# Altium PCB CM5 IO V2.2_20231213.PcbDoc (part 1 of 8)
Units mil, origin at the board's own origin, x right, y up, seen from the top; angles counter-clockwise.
Board outline 6299.61 x 3544.09 mil, 4 copper layers (Top, GND, Power, Bottom), stack 35.4 mil thick; 482 components, 404 nets, 1857 pads, 2731 vias.
Unrouted connection lines stored in the file: 1872.
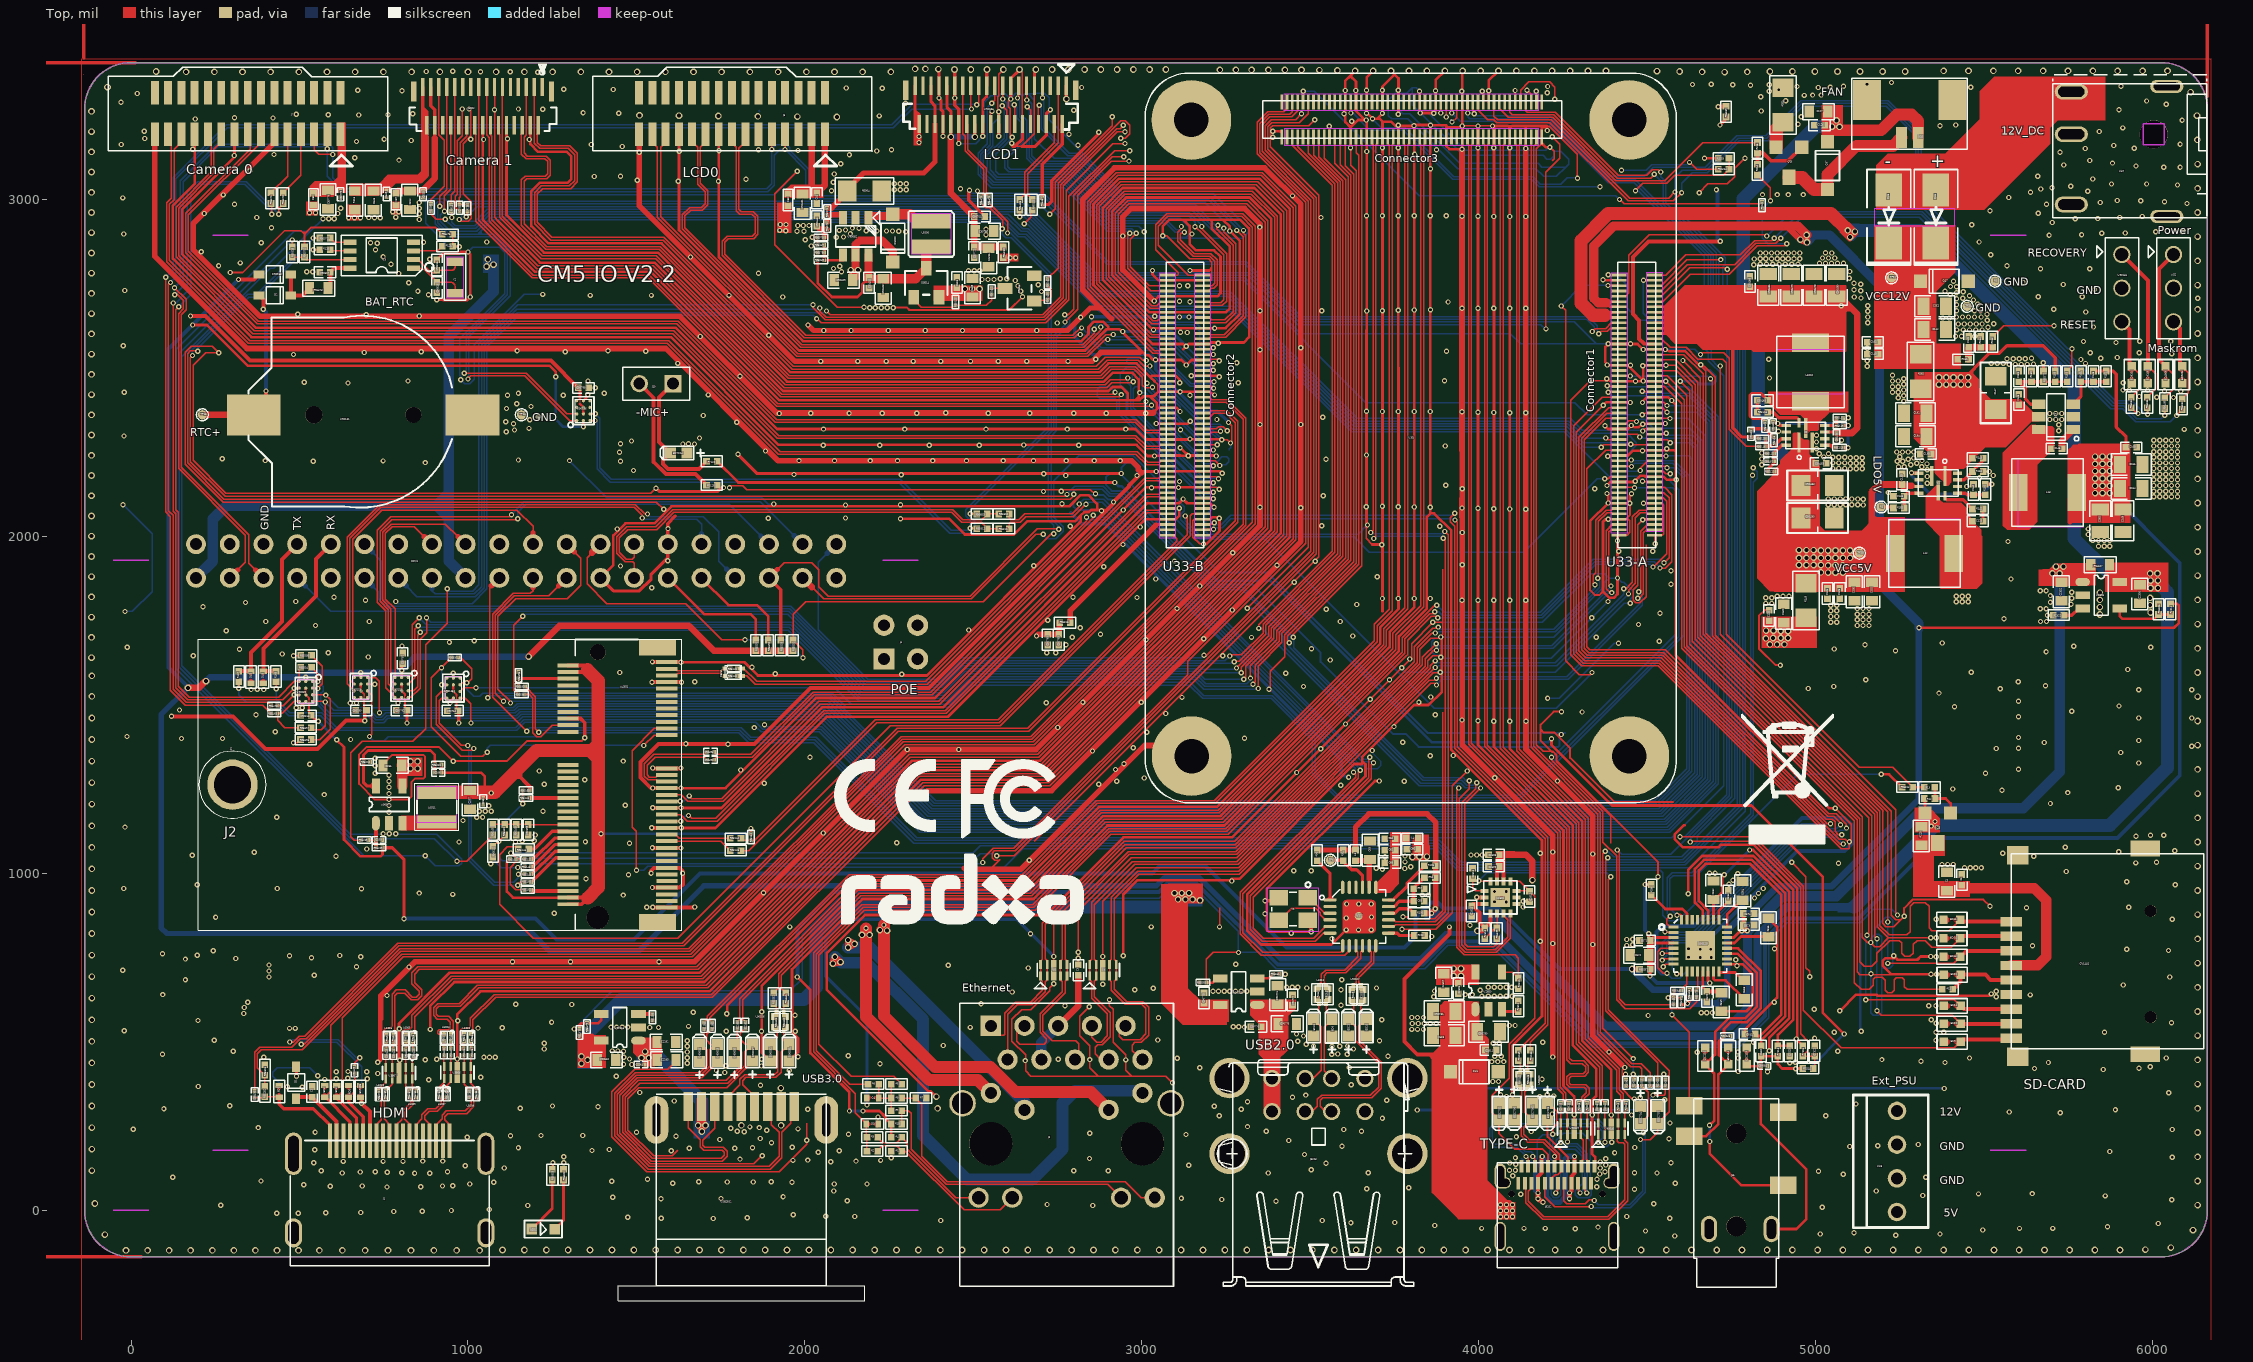
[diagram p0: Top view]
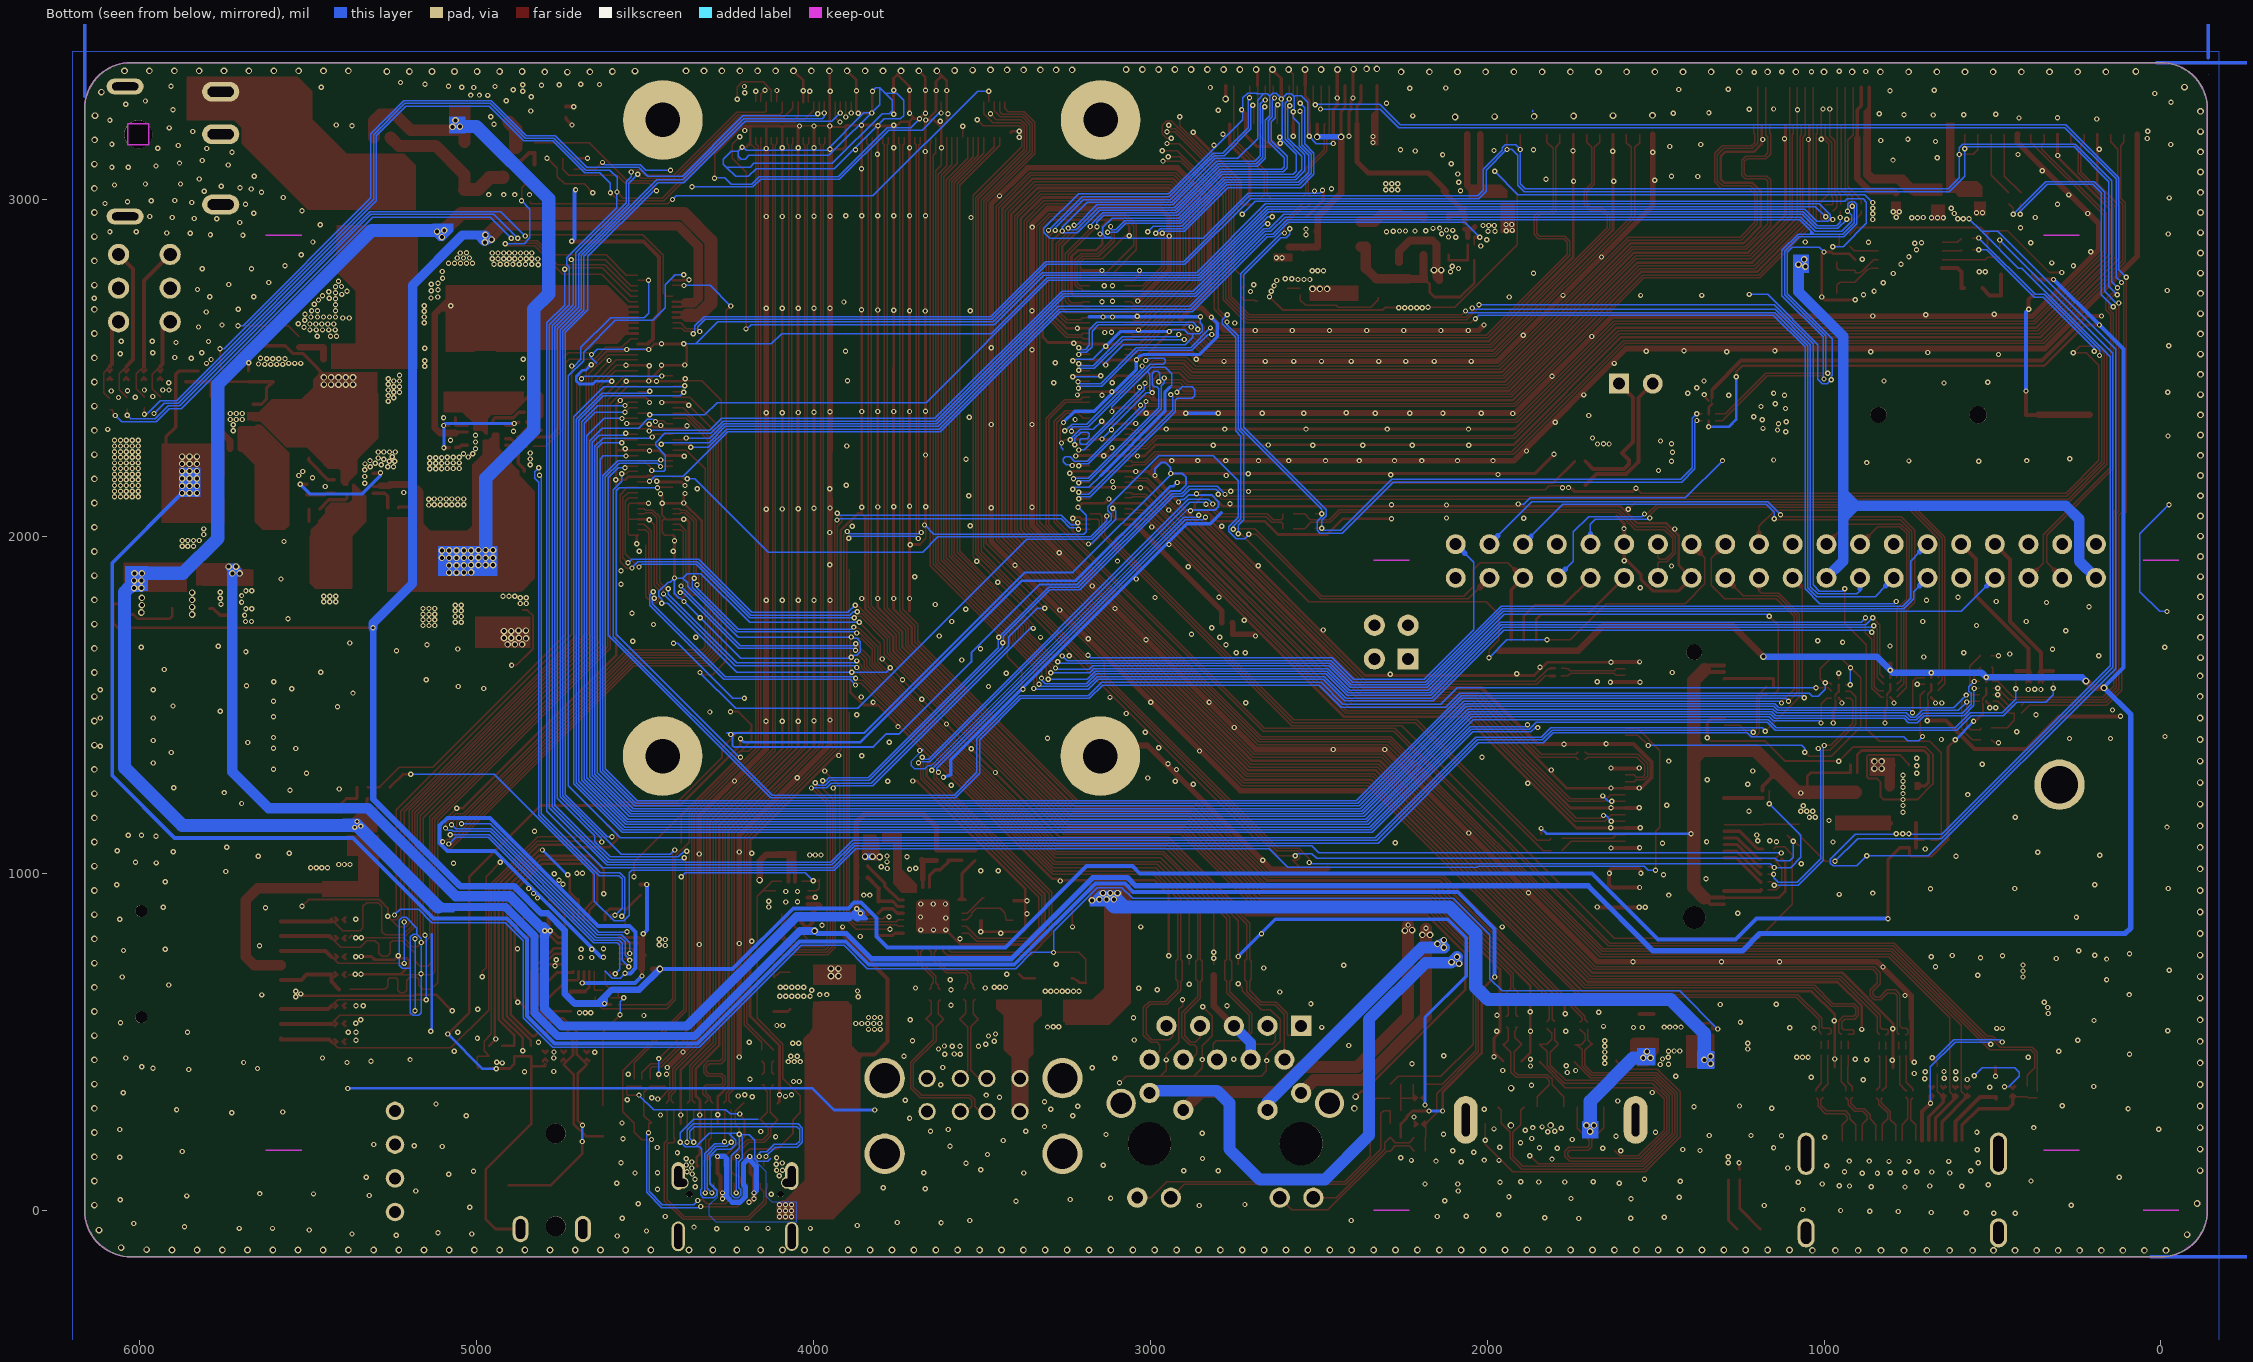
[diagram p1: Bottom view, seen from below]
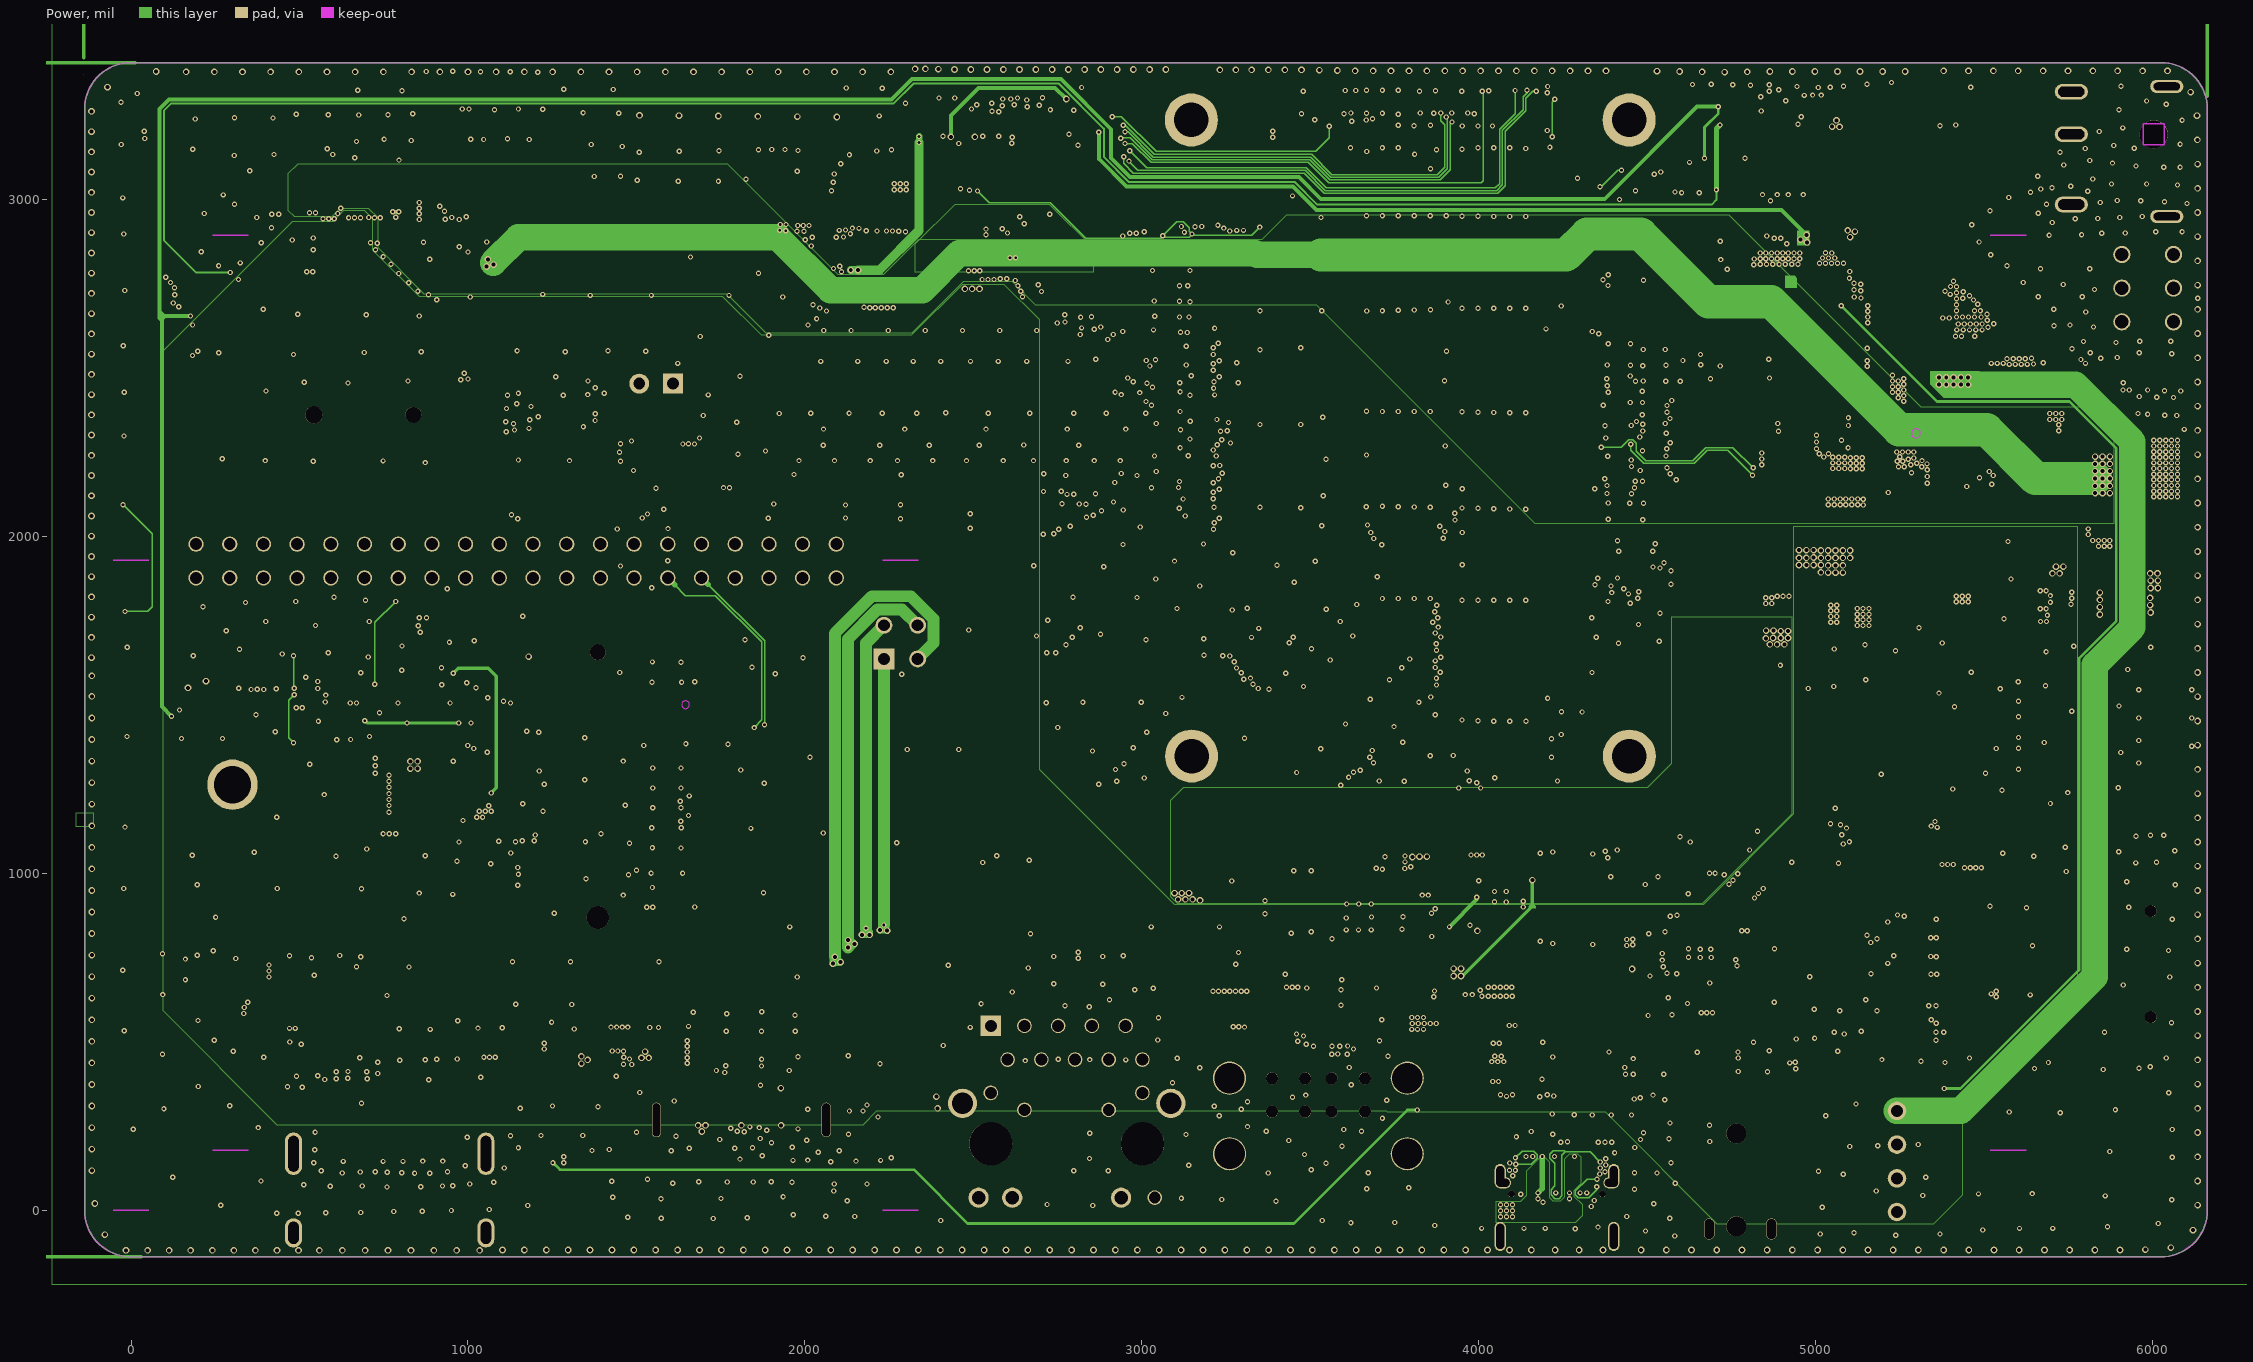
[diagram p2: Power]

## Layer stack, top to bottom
Solder Mask Top: solder mask 0.4, Solder Resist, Dk 3.5
Top: signal copper 1.35
Dielectric 1: dielectric 10, FR-4, Dk 4.3
GND: signal copper 1.35
Dielectric2: dielectric 10, FR-4, Dk 4.3
Power: signal copper 1.35
Dielectric3: dielectric 10, FR-4, Dk 4.3
Bottom: signal copper 1.35
Solder Mask Bottom: solder mask 0.4, Solder Resist, Dk 3.5

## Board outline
-137.8,3267.72 cw(c0,3267.72) 0,3405.51 6024.02,3405.51 cw(c6024.02,3267.72) 6161.81,3267.72 6161.81,-0.79 cw(c6024.02,-0.79) 6024.02,-138.58 0,-138.58 cw(c0,-0.79) -137.8,-0.79

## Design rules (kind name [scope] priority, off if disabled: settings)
Clearance "Clearance - Default - DEFAULT- SMD" [IsVia vs IsSMTPin] p1: gap=0 ignorepadtopadclearanceinfootprint=FALSE
Clearance "Clearance - Default - DEFAULT - Via" [IsVia vs IsVia] p2: gap=0 ignorepadtopadclearanceinfootprint=FALSE
Clearance "Clearance - Default - DEFAULT - Net" [All] p3: gap=3.94 ignorepadtopadclearanceinfootprint=FALSE except(0: Arc-Hole Track-Hole SMDPad-Hole THPad-Hole Via-Hole Fill-Hole Poly-Hole Region-Hole Text-Hole; 5.91: Arc-Fill Arc-Poly Arc-Region Track-Fill Track-Poly Track-Region SMDPad-Fill SMDPad-Poly SMDPad-Region THPad-Fill THPad-Poly THPad-Region Via-Fill Via-Poly Via-Region; 10: Fill-Fill Fill-Poly Fill-Region Poly-Poly Poly-Region Region-Region Text-Text)
ComponentClearance "ComponentClearance - Default - DEFAULT" [All] p1: gap=0 collisioncheckmode=3 verticalgap=10 showdistances=FALSE
FanoutControl Fanout_SOIC [IsSOIC] p1: bgadir=Out bgaviamode=Centered fanoutstyle=Auto fanoutdirection=Alternating viagrid=1 // Fanout_SOIC (Default Rule)
FanoutControl Fanout_Small [(CompPinCount < 5)] p2: bgadir=Out bgaviamode=Centered fanoutstyle=Auto fanoutdirection=OutThenIn viagrid=1 // Fanout_Small (Default Rule)
FanoutControl Fanout_LCC [IsLCC] p3: bgadir=Out bgaviamode=Centered fanoutstyle=Auto fanoutdirection=Alternating viagrid=1 // Fanout_LCC (Default Rule)
FanoutControl Fanout_BGA [IsBGA] p4: bgadir=Out bgaviamode=Centered fanoutstyle=Auto fanoutdirection=Alternating viagrid=1 // Fanout_BGA (Default Rule)
HoleToHoleClearance "HoleToHoleClearance - Default - DEFAULT" [All] p1: gap=0 allowstackedmicrovias=TRUE
Length "Length - NetClass - MLNetGroup6" [InNetClass('MLNetGroup6')] p1: maxlimit=18503.27 minlimit=0
Length "Length - NetClass - MLNetGroup2" [InNetClass('MLNetGroup2')] p2: maxlimit=18503.27 minlimit=0
Length "Length - NetClass - MLNetGroup10" [InNetClass('MLNetGroup10')] p3: maxlimit=18503.27 minlimit=0
Length "Length - NetClass - MLNetGroup9" [InNetClass('MLNetGroup9')] p4: maxlimit=18503.27 minlimit=0
Length "Length - NetClass - MLNetGroup11" [InNetClass('MLNetGroup11')] p5: maxlimit=18503.27 minlimit=0
Length "Length - NetClass - MLNetGroup1" [InNetClass('MLNetGroup1')] p6: maxlimit=18503.27 minlimit=0
Length "Length - NetClass - MLNetGroup7" [InNetClass('MLNetGroup7')] p7: maxlimit=18503.27 minlimit=0
Length "Length - NetClass - MLNetGroup5" [InNetClass('MLNetGroup5')] p8: maxlimit=18503.27 minlimit=0
Length "Length - NetClass - MLNetGroup3" [InNetClass('MLNetGroup3')] p9: maxlimit=18503.27 minlimit=0
Length "Length - NetClass - MLNetGroup4" [InNetClass('MLNetGroup4')] p10: maxlimit=18503.27 minlimit=0
Length "Length - NetClass - MLNetGroup8" [InNetClass('MLNetGroup8')] p11: maxlimit=18503.27 minlimit=0
Length "Default Length" [All] p12: maxlimit=50000 minlimit=0
MatchedLengths "MatchedLengths - NetClass - MLNetGroup6" [InNetClass('MLNetGroup6')] p1: tolerance=200 checknetsindiffpair=FALSE checkdiffpairvsdiffpair=TRUE checkxsignals=TRUE checkothers=TRUE
MatchedLengths "MatchedLengths - NetClass - MLNetGroup2" [InNetClass('MLNetGroup2')] p2: tolerance=200 checknetsindiffpair=FALSE checkdiffpairvsdiffpair=TRUE checkxsignals=TRUE checkothers=TRUE
MatchedLengths "MatchedLengths - NetClass - MLNetGroup10" [InNetClass('MLNetGroup10')] p3: tolerance=200 checknetsindiffpair=FALSE checkdiffpairvsdiffpair=TRUE checkxsignals=TRUE checkothers=TRUE
MatchedLengths "MatchedLengths - NetClass - MLNetGroup9" [InNetClass('MLNetGroup9')] p4: tolerance=200 checknetsindiffpair=FALSE checkdiffpairvsdiffpair=TRUE checkxsignals=TRUE checkothers=TRUE
MatchedLengths "MatchedLengths - NetClass - MLNetGroup11" [InNetClass('MLNetGroup11')] p5: tolerance=200 checknetsindiffpair=FALSE checkdiffpairvsdiffpair=TRUE checkxsignals=TRUE checkothers=TRUE
MatchedLengths "MatchedLengths - NetClass - MLNetGroup1" [InNetClass('MLNetGroup1')] p6: tolerance=200 checknetsindiffpair=FALSE checkdiffpairvsdiffpair=TRUE checkxsignals=TRUE checkothers=TRUE
MatchedLengths "MatchedLengths - NetClass - MLNetGroup7" [InNetClass('MLNetGroup7')] p7: tolerance=200 checknetsindiffpair=FALSE checkdiffpairvsdiffpair=TRUE checkxsignals=TRUE checkothers=TRUE
MatchedLengths "MatchedLengths - NetClass - MLNetGroup4" [InNetClass('MLNetGroup4')] p8: tolerance=200 checknetsindiffpair=FALSE checkdiffpairvsdiffpair=TRUE checkxsignals=TRUE checkothers=TRUE
MatchedLengths "MatchedLengths - NetClass - MLNetGroup3" [InNetClass('MLNetGroup3')] p9: tolerance=200 checknetsindiffpair=FALSE checkdiffpairvsdiffpair=TRUE checkxsignals=TRUE checkothers=TRUE
MatchedLengths "MatchedLengths - NetClass - MLNetGroup8" [InNetClass('MLNetGroup8')] p10: tolerance=200 checknetsindiffpair=FALSE checkdiffpairvsdiffpair=TRUE checkxsignals=TRUE checkothers=TRUE
MatchedLengths "MatchedLengths - NetClass - MLNetGroup5" [InNetClass('MLNetGroup5')] p11: tolerance=200 checknetsindiffpair=FALSE checkdiffpairvsdiffpair=TRUE checkxsignals=TRUE checkothers=TRUE
MaxMinImpedance "Default Impedance" [All] p1: minimum=50.00 maximum=150.0
ParallelSegment "Default Parallel Segment Same Layer" [All] p1: limit=1000 gap=200
ParallelSegment "Default Parallel Segment Adjasent" [All] p2: limit=1000 gap=200
PlaneClearance "PlaneClearance - FootPrint 'DIP4PIN-2_54MM-2X2'" [HasFootprint('DIP4PIN-2_54MM-2X2')] p1: clearance=7.5 // PAD - Power Plane Clearance
PlaneConnect "Default PlaneConnect" [All] p1: planeconnectstyle=Direct reliefexpansion=20 reliefentries=4 reliefconductorwidth=15 reliefairgap=10
PolygonConnect "PolygonConnect - Default SMT" [IsSMTPin] p1: connectstyle=Direct reliefconductorwidth=10 reliefentries=4 polygonreliefangle="45 Angle" airgapwidth=10
PolygonConnect "PolygonConnect - Default Pad" [All] p2: connectstyle=Direct reliefconductorwidth=15 reliefentries=4 polygonreliefangle="45 Angle" airgapwidth=10
RoutingLayers "RoutingLayers - Default - DEFAULT" [All] p1: top layer_v5=TRUE mid layer 1_v5=TRUE mid layer 2_v5=TRUE bottom layer_v5=TRUE
RoutingPriority "RoutingPriority - Default - DEFAULT" [All] p1: routingpriority=3
RoutingTopology "Default Routing Topology" [All] p1: topology=Shortest
RoutingVias "RoutingVias - Default - DEFAULT" [All] p1: holewidth=7.87 width=15.75 viastyle="Through Hole" minholewidth=7.87 minwidth=15.75 maxholewidth=7.87 maxwidth=15.75
SMDToCorner "SMDToCorner - Default - DEFAULT" [All] p1: distance=0
SolderMaskExpansion [All] p1: expansion=4 istentingtop=FALSE
Width "Width - Net - N16766319" [InNet('N16766319') OR InNet('MIC_IN2P') OR InNet('N16766259') OR InNet('HPOR') OR InNet('HPOL')] p1: maxlimit=196.85 minlimit=3.94 preferedwidth=7.87
Width "Default Width" [All] p2: maxlimit=196.85 minlimit=3.94 preferedwidth=3.94
18 further rules are at their usual default settings.

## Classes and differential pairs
net class MLNetGroup3: MIPI_DPHY0_TX_CLKN MIPI_DPHY0_TX_CLKP MIPI_DPHY0_TX_D0N MIPI_DPHY0_TX_D0P MIPI_DPHY0_TX_D1N MIPI_DPHY0_TX_D1P
net class MLNetGroup4: PHY1_MDI0+ PHY1_MDI0- PHY1_MDI1+ PHY1_MDI1- PHY1_MDI2+ PHY1_MDI2- PHY1_MDI3+ PHY1_MDI3-
net class MLNetGroup8: HDMI0_TX1N HDMI0_TX1P HDMI0_TX2N HDMI0_TX2P
net class MLNetGroup5: SDMMC_CLK SDMMC_CMD SDMMC_D0 SDMMC_D1 SDMMC_D2 SDMMC_D3
net class MLNetGroup2: MIPI_DPHY0_RX_CLKN MIPI_DPHY0_RX_CLKP MIPI_DPHY0_RX_D0N MIPI_DPHY0_RX_D0P MIPI_DPHY0_RX_D1N MIPI_DPHY0_RX_D1P MIPI_DPHY0_RX_D2N MIPI_DPHY0_RX_D2P MIPI_DPHY0_RX_D3N MIPI_DPHY0_RX_D3P
net class MLNetGroup10: TYPEC0_SSRX2N TYPEC0_SSRX2P TYPEC0_SSTX2N TYPEC0_SSTX2P TYPEC_SSRX2N TYPEC_SSRX2P TYPEC_SSTX2N TYPEC_SSTX2P
net class MLNetGroup6: MIPI_DPHY1_TX_CLKN MIPI_DPHY1_TX_CLKP MIPI_DPHY1_TX_D0N MIPI_DPHY1_TX_D0P MIPI_DPHY1_TX_D1N MIPI_DPHY1_TX_D1P MIPI_DPHY1_TX_D2N MIPI_DPHY1_TX_D2P
net class MLNetGroup1: MIPI_CSI0_RX_CLK0N MIPI_CSI0_RX_CLK0P MIPI_CSI0_RX_D0N MIPI_CSI0_RX_D0P MIPI_CSI0_RX_D1N MIPI_CSI0_RX_D1P
net class MLNetGroup7: HDMI0_TX0N HDMI0_TX0P HDMI0_TX3N HDMI0_TX3P
net class MLNetGroup11: TYPEC0_SSRX1N TYPEC0_SSRX1P TYPEC0_SSTX1N TYPEC0_SSTX1P TYPEC_SSRX1N TYPEC_SSRX1P TYPEC_SSTX1N TYPEC_SSTX1P
net class MLNetGroup9: SSRX_1N SSRX_1P SSTX_1N SSTX_1P USB30_2_SSRXN USB30_2_SSRXP USB30_2_SSTXN USB30_2_SSTXP

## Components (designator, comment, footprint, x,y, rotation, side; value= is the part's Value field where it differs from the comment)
C1 "C0402" C0402 537.4,351.38 r90 top
C3 "C0402" C0402 2811.23,712.36 r270 top
C4 "C0603" C0603 5388.78,975.39 r90 top
C5 "C0402" C0402 5433.07,980.31 r90 top
C34 "C0402" C0402 2035.43,3002.95 r270 top
C83 "C0603" C0603 3677.17,1067.91 r270 top
C84 "C0402" C0402 3736.22,1102.36 r180 top
C85 "C0402" C0402 3802.17,1070.87 r180 top
C87 "C0402" C0402 3736.22,1067.91 r180 top
C88 "C0402" C0402 3736.22,1030.51 r180 top
C89 "C0402" C0402 3821.85,916.34 r0 top
C126 "C0402" C0402 5010.83,3219.49 r0 top
C127 "C0603" C0603 5007.87,3259.84 r0 top
C129 "C0402" C0402 5480.31,2044.29 r180 top
C130 "C0603" C0603 4904.53,1770.67 r90 top
C131 "C0402" C0402 4861.22,1764.76 r90 top
C132 "C0805" C0805 5295.28,2365.16 r180 top
C133 "C0402" C0402 5325.79,2244.09 r180 top
C134 "C0805" C0805 5295.28,2296.26 r180 top
C135 "C0402" C0402 5034.45,1829.72 r270 top
C136 "C0603" C0603 5114.17,1835.63 r270 top
C137 "C0603" C0603 5166.34,1835.63 r270 top
C138 "C0402" C0402 5070.87,1829.72 r270 top
C139 "C0402" C0402 5255.91,2169.29 r90 top
C140 "C0402" C0402 5168.31,2540.35 r180 top
C141 "C0402" C0402 5453.74,2576.77 r90 top
C142 "C0805" C0805 5352.36,2613.19 r0 top
C143 "C0402" C0402 5246.06,2118.11 r180 top
C144 "C0402" C0402 5467.52,2138.78 r90 top
C145 "C0402" C0402 5714.57,2259.84 r180 top
C146 "C0402" C0402 5602.36,2405.51 r90 top
C147 "C1206" C1206 5533.46,2425.2 r90 top
C148 "C0402" C0402 5823.82,2474.41 r270 top
C149 "C0805" C0805 5911.42,2046.26 r270 top
C150 "C0402" C0402 5936.02,2263.78 r0 top
C151 "C0805" C0805 5352.36,2682.09 r180 top
C152 "C0402" C0402 5168.31,2575.79 r180 top
C153 "C0402" C0402 5602.36,2474.41 r90 top
C154 "C0805" C0805 5936.02,2141.73 r0 top
C155 "C0805" C0805 5936.02,2212.6 r0 top
C156 "C0805" C0805 5843.5,2046.26 r270 top
C265 "C0603" C0603 775.55,1319.87 r180 top
C266 "C0201" C0201 911.42,1298.23 r180 top
C267 "C0603" C0603 1005.91,1217.52 r270 top
C268 "C0201" C0201 1045.28,1213.58 r270 top
C269 "C0201" C0201 736.22,1098.43 r0 top
C548 "C0603" C0603 719,2996.56 r270 top
C549 "C0201" C0201 757.87,3015.75 r270 top
C558 "C0402" C0402 2450.79,2752.95 r90 top
C559 "C0603" C0603 2497.05,2737.2 r90 top
C560 "C0402" C0402 4837.6,472.44 r270 top
C561 "C0402" C0402 4804.13,522.64 r180 top
C562 "C0603" C0603 4696.05,949.44 r90 top
C563 "C0402" C0402 4740.16,933.07 r90 top
C564 "C0603" C0603 4782.66,947.47 r90 top
C565 "C0603" C0603 4859.25,838.58 r90 top
C568 "C0603" C0603 4787.4,654.53 r90 top
C569 "C0603" C0603 4719.67,617.74 r270 top
C570 "C0402" C0402 4676.36,633.49 r270 top
C571 "C0402" C0402 4492.13,800.2 r180 top
C572 "C0603" C0603 4476.38,756.89 r180 top
C573 "C0402" C0402 4800.38,846.09 r0 top
C574 "C0402" C0402 4800.38,880.54 r0 top
C658 "C0805" C0805 3896.65,518.7 r180 top
C750 "C0201" C0201 974.41,2974.41 r90 top
C812 "C0603" C0603 827.76,2997.05 r270 top
C813 "C0201" C0201 866.14,3014.76 r270 top
C2010 "C0201" C0201 4507.87,377.95 r270 top
C2011 "C0201" C0201 4483.27,377.95 r270 top
C2013 "C0201" C0201 4349.79,308.07 r270 top
C2014 "C0201" C0201 4373.42,308.07 r270 top
C2019 "C0201" C0201 4243.12,308.06 r270 top
C2020 "C0201" C0201 4266.74,308.06 r270 top
C2280 "C0201" C0201 1799.21,549.21 r270 top
C2281 "C0201" C0201 1822.83,549.21 r270 top
C2282 "C0603" C0603 1588.58,499.02 r0 top
C2283 "C0603" C0603 1589.57,445.87 r0 top
C2284 "C0201" C0201 1513.78,432.09 r180 top
C2330 "C0603" C0603 5961.61,1828.74 r270 top
C2332 "C0603" C0603 5728.35,1835.63 r270 top
C2335 "C0603" C0603 2545.27,2826.77 r270 top
C2606 "C0402" C0402 3938.98,657.48 r270 top
C2607 "C0603" C0603 3895.67,674.21 r270 top
C2608 "C0402" C0402 4044.29,1055.12 r180 top
C2609 "C0402" C0402 4044.29,1019.68 r180 top
C2611 "C0402" C0402 4035.43,475.39 r0 top
C2612 "C0402" C0402 4150.22,930.87 r270 top
C2613 "C0402" C0402 3980.93,998.79 r90 top
C2614 "C0402" C0402 3978.35,887.8 r270 top
C7320 "C0402" C0402 4922.24,472.44 r270 top
C7322 "C0402" C0402 4996.06,472.44 r90 top
C90084 "C0201" C0201 4846.46,428.15 r0 top
C90392 "C0201" C0201 1719.49,1336.61 r180 top
C90393 "C0201" C0201 1719.49,1360.24 r180 top
C90399 "C0402" C0402 1179.09,1128.92 r270 top
C90408 "C0603" C0603 2232.28,2736.22 r270 top
C90409 "C0603" C0603 2114.17,2759.84 r180 top
C90410 "C0402" C0402 2189.96,2751.97 r270 top
C90420 "C0201" C0201 928.15,469.49 r270 top
C90421 "C0201" C0201 837.6,467.52 r270 top
C90422 "C0201" C0201 814.96,467.52 r270 top
C90423 "C0201" C0201 756.89,467.52 r270 top
C90424 "C0201" C0201 778.54,467.52 r270 top
C90425 "C0201" C0201 1009.84,469.49 r270 top
C90426 "C0201" C0201 987.2,469.49 r270 top
C90427 "C0201" C0201 948.82,469.49 r270 top
C90429 "C0201" C0201 663.39,415.35 r270 top
C90430 "C0201" C0201 367.13,343.5 r270 top
C90431 "C0603" C0603 1992.13,2988.19 r270 top
C90448 "C0402" C0402 2035.43,2935.04 r90 top
C90478 "C0805" C0805 4994.09,2745.08 r90 top
C90479 "C0805" C0805 4927.17,2745.08 r90 top
C90480 "C1206" C1206 5004.92,2054.13 r0 top
C90481 "C0201" C0201 4807.09,2304.13 r270 top
C90482 "C0201" C0201 4873.03,2328.74 r270 top
C90483 "C0402" C0402 5014.76,2216.54 r0 top
C90484 "C1206" C1206 5004.92,2150.59 r0 top
C90485 "C0805" C0805 4858.27,2745.08 r90 top
C90486 "C0201" C0201 5061.02,2296.26 r270 top
C90487 "C0201" C0201 4865.16,2222.44 r180 top
C90488 "C0402" C0402 4804.13,2755.91 r90 top
C90489 "C0402" C0402 4841.54,2403.54 r0 top
C90490 "C0805" C0805 5062.01,2745.08 r90 top
C90582 "C0603" C0603 1410.89,445.56 r180 top
C90615 "C0402" C0402 907.48,2738.19 r270 top
C90616 "C0402" C0402 907.48,2805.12 r90 top
C90617 "C0402" C0402 575.79,2783.46 r180 top
C90618 "C0402" C0402 518.7,1468.5 r0 top
C90750 "C0603" C0603 2532.48,2905.51 r0 top
C90751 "C0402" C0402 2517.71,2948.82 r0 top
C90772 "C0402" C0402 2501.97,2842.52 r270 top
C90773 "C0402" C0402 3184.06,629.92 r90 top
C90774 "C0603" C0603 3402.56,638.78 r90 top
C90775 "C0603" C0603 3431.33,552.93 r0 top
C90776 "C0402" C0402 3338.58,544.29 r180 top
C90777 "C0402" C0402 3446.85,624.02 r90 top
C90778 "C0603" C0603 584.65,2999.02 r270 top
C90779 "C0201" C0201 622.05,3014.76 r270 top
C90780 "C0805" C0805 4028.54,529.53 r0 top
C90781 "C0805" C0805 3896.65,589.57 r180 top
C90782 "C0402" C0402 803.15,1483.27 r0 top
C90783 "C0402" C0402 683.07,1483.27 r0 top
C90784 "C0402" C0402 954.72,1482.28 r0 top
C90787 "C0402" C0402 806.1,1637.8 r270 top
C90788 "C0402" C0402 1342.87,2440.33 r180 top
C90789 "C0402" C0402 2752.95,1692.91 r270 top
C90790 "C0402" C0402 2720.47,1692.91 r270 top
CN14A1 "TF-CKT01-009D" TF-CKT01-009D 5993.5,730.31 r0 top
CON1 "DIP40PIN_2D54MM" DIP40PIN_2D54MM 192.94,1976.36 r0 top
D1 "SOD_323" SOD_323 490.16,377.95 r270 top
D2 "SOD_323" SOD_323 427.17,2714.92 r0 top
D3 "ESD0402_1XD5" ESD0402_1XD5 2199.8,255.91 r180 top
D4 "ESD0402_1XD5" ESD0402_1XD5 2200.79,332.68 r0 top
D37 "SOD_123" SOD_123 5034.45,3099.41 r90 top
D41 "SOD_123" SOD_123 3986.22,410.43 r180 top
D45 "DO_214AC" DO_214AC 5356.3,2948.82 r270 top
D46 "DO_214AC" DO_214AC 5216.54,2948.82 r270 top
D47 "SOD_123" SOD_123 5380.91,2756.89 r180 top
D48 "ESD0402_1XD5" ESD0402_1XD5 392.72,1581.69 r90 top
D49 "ESD0402_1XD5" ESD0402_1XD5 356.3,1581.69 r90 top
D5000 "SOD_123" SOD_123 2260.82,2884.84 r270 top
D90031 "ESD0402" ESD0402 1952.76,467.52 r270 top
D90032 "ESD0402" ESD0402 1896.65,467.52 r270 top
D90033 "ESD0402" ESD0402 1740.16,466.54 r270 top
D90034 "ESD0402" ESD0402 1687.01,466.54 r270 top
D90035 "ESD0402" ESD0402 1790.35,466.54 r270 top
D90037 "ESD0402" ESD0402 1844.49,467.52 r270 top
D90038 "SOD_323" SOD_323 427.17,2776.57 r0 top
ED1 "ESD0402_1XD5" ESD0402_1XD5 439.96,352.36 r90 top
ED2 "ESD0402_1XD5" ESD0402_1XD5 574.8,352.36 r90 top
ED3 "ESD0402_1XD5" ESD0402_1XD5 610.24,352.36 r90 top
ED5 "ESD0402_1XD5" ESD0402_1XD5 645.67,352.36 r90 top
ED6 "ESD0402" ESD0402 3563.98,541.34 r270 top
ED9 "E0402N" E0402N 5404.53,500 r180 top
ED10 "E0402N" E0402N 5404.53,553.15 r180 top
ED11 "E0402N" E0402N 5404.53,606.3 r180 top
ED12 "E0402N" E0402N 5404.53,698.82 r180 top
ED13 "E0402N" E0402N 5403.54,751.97 r180 top
ED14 "E0402N" E0402N 5403.54,807.09 r180 top
ED15 "E0402N" E0402N 5403.54,862.2 r180 top
ED20 "ESD0402" ESD0402 3665.7,541.59 r270 top
ED21 "ESD0402" ESD0402 3612.55,541.59 r270 top
ED22 "ESD0402" ESD0402 3509.16,541.52 r270 top
ED2109 "E0402N" E0402N 4795.28,457.68 r90 top
ED2110 "E0402N" E0402N 4671.35,457.3 r90 top
ED2111 "E0402N" E0402N 4740.16,457.68 r90 top
ED4806 "E0402N" E0402N 6037.4,2479.33 r270 top
ED7104 "ESD0402" ESD0402 1625,2247.05 r0 top
ED9203 "E0402N" E0402N 6086.61,2479.33 r270 top
ED9204 "E0402N" E0402N 5937.01,2479.33 r270 top
ED9205 "E0402N" E0402N 5985.24,2479.33 r270 top
ED9206 "ESD0402_1XD5" ESD0402_1XD5 681.1,352.36 r90 top
ESD2701 "ESD0402" ESD0402 4530.51,282.48 r90 top
ESD2702 "ESD0402" ESD0402 4060.04,292.32 r90 top
ESD2703 "ESD0402" ESD0402 4203.74,292.32 r90 top
ESD2704 "ESD0402" ESD0402 4479.33,282.48 r90 top
ESD2706 "ESD0402" ESD0402 4104.57,292.65 r90 top
ESD27052 "ESD0402" ESD0402 4158.7,292.65 r90 top
FB2 "L0402" L0402 541.34,3000 r90 top
FB6 "L0402" L0402 1949.8,2998.03 r90 top
FB7 "L0402" L0402 786.42,3000 r90 top
FB261 "MCZ1210AH900L2" MCZ1210AH900L2 1812.01,1585.63 r90 top
J1 "HDMIA19S" HDMIA19S 767.72,206.69 r180 top
J2 "HOLE_D5_3D" HOLE_D5_3D 301.18,1262.6 r0 top
J3 "RJ45_HRK1" RJ45_HRK1 2551.39,547.01 r0 top
J4 "DIP4PIN-2_54MM-2X2" DIP4PIN-2_54MM-2X2 2234.28,1635.81 r90 top
J6 "FPC15PIN-1.0MM-LS" FPC15PIN-1.0MM-LS 2059.06,3192.91 r180 top
J7 "FPC15PIN-1.0MM-LS" FPC15PIN-1.0MM-LS 622.05,3192.91 r180 top
J10 "DIP2PIN-2P54MM" DIP2PIN-2P54MM 1608.27,2452.76 r270 top
J15 "PJ-327A" PJ-327A 4763.81,-48.05 r90 top
J24 "DF40C_100DS" DF40C_100DS 4245.47,3292.13 r270 top
J5002 "FH35C_31P_0_6SHW" FH35C_31P_0_6SHW 1220.47,3332.68 r180 top
J8202 "TYPEC-24PIN-SMD-OK" TYPEC-24PIN-SMD-OK 4063.14,-77.76 r0 top
J8203 "USB_DUAL" USB_DUAL 3523.65,167.31 r90 top
L3 "R0402" R0402 3633.86,1053.15 r90 top
L4 "L0402" L0402 3802.17,1104.33 r180 top
L12 "IND-5020" IND-5020 5321.85,1948.82 r180 top
L13 "IND-5020" IND-5020 5687.01,2129.92 r0 top
L5000 "IND_3X3" IND_3X3 2375,2896.65 r0 top
L5002 "IND-5020" IND-5020 4984.25,2487.2 r90 top
L5003 "SMD_TCM0605T" SMD_TCM0605T 1007.87,523.62 r270 top
L5004 "SMD_TCM0605T" SMD_TCM0605T 947.83,522.64 r270 top
L5005 "SMD_TCM0605T" SMD_TCM0605T 835.63,521.65 r270 top
L5006 "SMD_TCM0605T" SMD_TCM0605T 777.56,521.65 r270 top
L5007 "SMD_TCM0605T" SMD_TCM0605T 935.04,355.31 r270 top
L5008 "SMD_TCM0605T" SMD_TCM0605T 1023.62,355.31 r270 top
L5009 "SMD_TCM0605T" SMD_TCM0605T 845.47,355.31 r270 top
L5010 "SMD_TCM0605T" SMD_TCM0605T 754.92,355.31 r270 top
L5011 "IND_303015" IND_303015 907.48,1196.85 r90 top
L5012 "MCZ1210AH900L2" MCZ1210AH900L2 3524.91,616.33 r0 top
L90020 "MCZ1210AH900L2" MCZ1210AH900L2 4144.69,412.4 r180 top
L90026 "MCZ1210AH900L2" MCZ1210AH900L2 1937.01,583.66 r180 top
L90027 "MCZ1210AH900L2" MCZ1210AH900L2 3649.95,663.64 r180 top
LED4 "LED0603" LED0603 1223.43,-56.1 r0 top
P4 "TP_0R70" TP_0R70 5192.91,2086.61 r180 top
P6 "TP_0R70" TP_0R70 5531.5,2756.89 r180 top
Q1 "SOT23" SOT23 5361.63,1134.33 r180 top
Q15 "SOT23" SOT23 4919.93,3109.78 r180 top
Q9514 "SOT_23" SOT_23 2360.24,2751.97 r0 top
Q9515 "SOT_23" SOT_23 2636.81,2735.24 r90 top
R1 "R0402" R0402 2271.65,175.2 r0 top
R2 "R0402" R0402 2199.8,175.2 r180 top
R3 "R0402" R0402 2199.8,216.54 r0 top
R4 "R0402" R0402 2271.65,216.54 r180 top
R5 "R0402" R0402 2271.65,374.02 r180 top
R6 "R0402" R0402 2202.76,374.02 r0 top
R7 "R0402" R0402 2344.49,332.68 r180 top
R8 "R0402" R0402 2271.65,332.68 r180 top
R9 "R0402" R0402 2271.65,295.28 r0 top
R10 "R0402" R0402 2271.65,255.91 r180 top
R11 "R0402" R0402 5390.75,655.51 r0 top
R12 "R0402" R0402 5337.6,1221.46 r0 top
R13 "R0402" R0402 5337.11,1255.41 r180 top
R91 "R0402" R0402 3597.44,1053.15 r270 top
R94 "R0402" R0402 3854.33,986.22 r180 top
R96 "R0402" R0402 3519.69,1053.15 r270 top
R97 "R0402" R0402 3821.85,953.74 r180 top
R102 "R0402" R0402 3823.82,814.96 r0 top
R105 "R0402" R0402 3854.33,1021.65 r180 top
R106 "R0402" R0402 3822.04,881.2 r180 top
R120 "R0402" R0402 575.79,2850.39 r180 top
R121 "R0402" R0402 938.98,2860.24 r180 top
R147 "R0402" R0402 5480.31,2080.71 r0 top
R148 "R1206" R1206 4970.96,1809.55 r90 top
R149 "R0402" R0402 5480.31,2231.3 r180 top
R150 "R1206" R1206 5311.02,2489.17 r90 top
R151 "R0402" R0402 5437.01,2524.61 r180 top
R152 "R0402" R0402 5480.31,2191.93 r180 top
R153 "R0402" R0402 5524.61,2576.77 r270 top
R154 "R0402" R0402 5489.17,2576.77 r270 top
R155 "R0402" R0402 5246.06,2083.66 r0 top
R156 "R0402" R0402 5502.95,2138.78 r270 top
R157 "R0402" R0402 5861.22,2474.41 r270 top
R158 "R0402" R0402 5710.63,2474.41 r270 top
R159 "R0402" R0402 5746.06,2474.41 r270 top
R160 "R0402" R0402 5639.76,2474.41 r90 top
R161 "R0402" R0402 5786.42,2474.41 r90 top
R167 "R0402" R0402 319.88,1583.66 r270 top
R168 "R0402" R0402 430.12,1583.66 r270 top
R214 "R0402" R0402 4826.77,3087.6 r270 top
R215 "R0402" R0402 4826.77,3152.56 r90 top
R220 "R0603" R0603 5312.99,1110.24 r270 top
R249 "R0402" R0402 3622.39,639.03 r90 top
R250 "R0402" R0402 3655.85,639.03 r90 top
R253 "R0402" R0402 3519,640.93 r270 top
R254 "R0402" R0402 3552.47,640.93 r270 top
R316 "R0603" R0603 663.88,2996.56 r90 top
R353 "R1206" R1206 4902.56,3279.53 r90 top
R396 "R0402" R0402 4511.81,950.79 r270 top
R715 "R0201" R0201 998.03,2973.43 r90 top
R814 "R0201" R0201 949.8,2974.41 r90 top
R952 "R0201" R0201 1009.84,512.8 r270 top
R953 "R0201" R0201 987.2,512.8 r270 top
R954 "R0201" R0201 948.82,511.81 r270 top
R955 "R0201" R0201 928.15,511.81 r270 top
R956 "R0201" R0201 837.6,510.83 r270 top
R957 "R0201" R0201 814.96,510.83 r270 top
R958 "R0201" R0201 778.54,510.83 r270 top
R959 "R0201" R0201 757.87,510.83 r270 top
R2004 "R0201" R0201 4530.51,377.95 r270 top
R2005 "R0201" R0201 4553.15,377.95 r90 top
R2006 "R0201" R0201 4437.01,377.95 r90 top
R2007 "R0201" R0201 4459.65,377.95 r270 top
R2013 "R0201" R0201 4412.79,308.07 r270 top
R2015 "R0201" R0201 4436.41,308.07 r270 top
R2016 "R0201" R0201 4297.25,308.06 r270 top
R2017 "R0201" R0201 4320.87,308.06 r270 top
R2311 "R0402" R0402 6052.17,1783.46 r270 top
R2322 "R0402" R0402 5720.47,1765.75 r180 top
R2611 "R0402" R0402 4117.13,673.23 r270 top
R2612 "R0402" R0402 4117.13,605.31 r90 top
R2613 "R0402" R0402 4017.35,821.62 r270 top
R4203 "R0402" R0402 4726.38,3122.05 r180 top
R5004 "R1206" R1206 2176.18,3024.61 r0 top
R7120 "R0402" R0402 1723.43,2222.44 r180 top
R7125 "R0402" R0402 1723.43,2151.57 r0 top
R7313 "R0402" R0402 4886.81,472.44 r90 top
R7314 "R0402" R0402 4976.38,420.28 r180 top
R7315 "R0402" R0402 4960.63,472.44 r270 top
R9241 "R0201" R0201 4840.55,2982.28 r90 top
R90334 "R0402" R0402 4726.38,3088.58 r0 top
R90337 "R0201" R0201 4600.39,620.08 r90 top
R90338 "R0201" R0201 4737.2,516.73 r180 top
R90340 "R0201" R0201 4589.48,652.28 r180 top
R90341 "R0201" R0201 4577.76,620.08 r270 top
R91181 "R0201" R0201 1700.79,547.24 r270 top
R91182 "R0201" R0201 1724.48,547.34 r270 top
R91188 "R0402" R0402 4152.56,458.66 r270 top
R91189 "R0402" R0402 4117.13,458.66 r270 top
R91193 "R0201" R0201 1547.7,572.53 r270 top
R91375 "R0201" R0201 1330.71,527.56 r90 top
R95028 "R0402" R0402 478.35,2843.5 r90 top
R95039 "R0201" R0201 2047.24,2818.9 r0 top
R95041 "R0201" R0201 2446.85,2694.88 r270 top
R95042 "R0201" R0201 2719.49,2753.94 r270 top
R95043 "R0201" R0201 2719.49,2710.63 r90 top
R95044 "R0201" R0201 2554.13,2726.38 r90 top
R95071 "R0201" R0201 2065.94,2963.58 r90 top
R95072 "R0201" R0201 2065.94,2921.26 r90 top
R95073 "R0201" R0201 2047.24,2886.81 r0 top
R95113 "R0201" R0201 5069.88,2262.8 r180 top
R95114 "R0201" R0201 4865.16,2246.06 r0 top
R95115 "R0402" R0402 4841.54,2368.11 r180 top
R95116 "R0201" R0201 4840.55,2266.73 r180 top
R95117 "R0201" R0201 5070.87,2351.38 r0 top
R95118 "R0201" R0201 4875.98,2284.45 r270 top
R95119 "R0201" R0201 5070.87,2328.74 r180 top
R95120 "R0201" R0201 4840.55,2289.37 r0 top
R95121 "R0201" R0201 4849.41,2328.74 r270 top
R95122 "R0201" R0201 4867.13,2191.93 r0 top
R95137 "R0201" R0201 2047.24,2864.17 r0 top
R95141 "R0201" R0201 1788.88,1607.78 r0 top
R95142 "R0201" R0201 1788.88,1585.14 r0 top
R95143 "R0201" R0201 1172.2,1223.41 r0 top
R95144 "R0402" R0402 1794.29,1103.35 r180 top
R95145 "R0402" R0402 1165.31,1071.84 r0 top
R95146 "R0402" R0402 1794.29,1066.93 r180 top
R95147 "R0201" R0201 1177.13,1042.31 r0 top
R95148 "R0201" R0201 1177.13,1019.67 r0 top
R95149 "R0201" R0201 1177.13,997.03 r0 top
R95150 "R0201" R0201 1177.13,974.4 r0 top
R95151 "R0201" R0201 1839.57,1107.28 r90 top
R95152 "R0201" R0201 1177.13,950.77 r0 top
R95153 "R0201" R0201 1172.2,1246.05 r0 top
R95154 "R0201" R0201 1134.8,1042.31 r180 top
R95155 "R0402" R0402 1073.78,1128.92 r90 top
R95159 "R0402" R0402 1143.66,1128.92 r270 top
R95209 "R0201" R0201 736.22,1075.79 r180 top
R95210 "R0201" R0201 699.76,1329.71 r0 top
R95239 "R0201" R0201 692.91,1098.43 r0 top
R95263 "R0201" R0201 937.01,344.49 r270 top
R95264 "R0201" R0201 914.37,344.49 r270 top
R95265 "R0201" R0201 1025.59,344.49 r270 top
R95266 "R0201" R0201 1002.95,344.49 r270 top
R95267 "R0201" R0201 824.8,344.49 r270 top
R95268 "R0201" R0201 846.46,344.49 r270 top
R95269 "R0201" R0201 756.89,344.49 r270 top
R95270 "R0201" R0201 734.25,344.49 r270 top
R95281 "R0201" R0201 911.42,1321.85 r180 top
R95282 "R0402" R0402 397.15,351.87 r270 top
R95373 "R0603" R0603 557.09,2736.22 r0 top
R95374 "R0402" R0402 514.76,2843.5 r90 top
R95375 "R0402" R0402 938.98,2895.67 r0 top
R95377 "R0402" R0402 575.79,2884.84 r180 top
R95467 "R0201" R0201 2703.74,2994.09 r90 top
R95468 "R0402" R0402 2637.8,2983.27 r90 top
R95469 "R0201" R0201 425.2,1474.41 r180 top
R95470 "R0201" R0201 425.2,1497.05 r180 top
R95471 "R0201" R0201 2546.26,2998.03 r90 top
R95472 "R0201" R0201 2522.63,2998.03 r90 top
R95495 "R0402" R0402 6035.43,2394.68 r90 top
R95530 "R0402" R0402 2588.58,2842.52 r90 top
R95541 "R0402" R0402 2674.21,2983.27 r270 top
R95546 "R0402" R0402 4151.57,387.8 r270 top
R95547 "R0402" R0402 4117.13,387.8 r270 top
R95550 "R0402" R0402 1942.91,559.06 r270 top
R95551 "R0402" R0402 1942.91,628.94 r270 top
R95552 "R0402" R0402 1907.48,628.94 r270 top
R95553 "R0402" R0402 1908.46,559.06 r270 top
R95555 "R0201" R0201 3181.1,675.2 r180 top
R95556 "R0201" R0201 3398.62,700.79 r0 top
R95557 "R0402" R0402 4492.13,714.57 r0 top
R95558 "R0201" R0201 4624.38,642.9 r90 top
R95570 "R0402" R0402 451.77,3002.95 r90 top
R95571 "R0402" R0402 415.35,3002.95 r90 top
R95572 "R0402" R0402 5675.2,2474.41 r270 top
R95573 "R0201" R0201 4645.67,642.72 r270 top
R95578 "R0201" R0201 2047.24,2841.54 r0 top
R95579 "R0201" R0201 1353.35,545.28 r270 top
R95580 "R0201" R0201 889.76,2975.39 r90 top
R95581 "R0402" R0402 1109.21,1128.92 r90 top
R95582 "R0402" R0402 6086.61,2391.73 r90 top
R95583 "R0201" R0201 1159.45,1554.13 r180 top
R95584 "R0402" R0402 5936.02,2396.65 r90 top
R95585 "R0402" R0402 5983.27,2396.65 r90 top
R95586 "R0201" R0201 1158.43,1530.5 r0 top
R95587 "R0201" R0201 960.63,1639.76 r180 top
R95589 "R0402" R0402 4733.27,3259.84 r90 top
R95590 "R0402" R0402 1890.75,1676.18 r90 top
R95591 "R0402" R0402 1854.33,1676.18 r90 top
R95592 "R0402" R0402 1964.57,1676.18 r90 top
R95593 "R0402" R0402 1928.15,1676.18 r90 top
R95594 "R0402" R0402 519.69,1611.22 r180 top
R95595 "R0402" R0402 519.69,1646.65 r180 top
R95596 "R0402" R0402 518.7,1396.65 r180 top
R95597 "R0402" R0402 518.7,1432.09 r180 top
R95598 "R0201" R0201 1149.61,1587.6 r90 top
R95599 "R0402" R0402 4052.78,821.62 r90 top
R95602 "R0402" R0402 1283.46,105.31 r90 top
R95603 "R0402" R0402 1250,105.31 r270 top
R95606 "R0402" R0402 6016.73,1783.46 r270 top
R95607 "R0603" R0603 5843.5,1915.35 r180 top
R95609 "R0402" R0402 2525.59,2065.94 r0 top
R95610 "R0402" R0402 2590.55,2065.94 r180 top
R95611 "R0402" R0402 2590.55,2022.64 r0 top
R95612 "R0402" R0402 2525.59,2022.64 r180 top
R95613 "R0402" R0402 5271.16,1255.41 r0 top
R95614 "R0402" R0402 1073.82,1063.98 r270 top
R95615 "R0402" R0402 397.15,415.85 r90 top
R95616 "R0402" R0402 2771.65,1743.11 r180 top
TP6 "TP_0R70" TP_0R70 3559.06,1038.39 r0 top
TP9 "TP_0R70" TP_0R70 5224.41,2766.73 r0 top
TP10 "TP_0R70" TP_0R70 5128.94,1949.8 r180 top
TP11 "TP_0R70" TP_0R70 5448.82,2682.09 r0 top
TP14 "TP_0R70" TP_0R70 1158.46,2360.24 r0 top
TP16 "TP_0R70" TP_0R70 211.61,2360.24 r0 top
U1 "QFN12_2R00X3R00X1R00" QFN12_2R00X3R00X1R00 4969.49,2299.21 r90 top
U3 "MSOP8" MSOP8 744.09,2832.68 r180 top
U5 "SON10_2R50X1R00X0R50" SON10_2R50X1R00X0R50 2738.4,712.36 r0 top
U6 "SON10_2R50X1R00X0R50" SON10_2R50X1R00X0R50 2884.07,712.36 r0 top
U17 "QFN24" QFN24 3644.87,871.36 r270 top
U26 "SMD_1D25X2PIN_90" SMD_1D25X2PIN_90 5303.15,3183.07 r0 top
U27 "QFN12_2R00X3R00X1R00" QFN12_2R00X3R00X1R00 5363.19,2157.48 r270 top
U28 "XIAO_4PIN_2D54" XIAO_4PIN_2D54 5240.58,294.87 r270 top
U29 "SOT_23_6" SOT_23_6 5712.6,2354.33 r90 top
U32 "DIP3_1X2P54" DIP3_1X2P54 6061.05,2736.2 r270 top
U33 "DF40C-200DS-D4-OK" DF40C-200DS-D4-OK 3796.46,2291.54 r0 top
U37 "DC-044A" DC-044A 6159.45,3192.91 r90 top
U2305 "SOT_23_5" SOT_23_5 5846.46,1824.8 r0 top
U2602 "MLP14_2R50X2R50X0R80" MLP14_2R50X2R50X0R80 4063.61,927.92 r0 top
U2603 "SOT_23_5" SOT_23_5 4028.54,651.57 r90 top
U3806 "SON10_2R50X1R00X0R50" SON10_2R50X1R00X0R50 968.5,408.46 r0 top
U3807 "SON10_2R50X1R00X0R50" SON10_2R50X1R00X0R50 795.28,406.5 r180 top
U4301 "M2_NGFF_KEY_E_1" M2_NGFF_KEY_E_1 1443.12,1262.17 r270 top
U90040 "SON10_2R50X1R00X0R50" SON10_2R50X1R00X0R50 4393.1,242.12 r0 top
U90077 "SOT_23_5" SOT_23_5 765.71,1203.73 r90 top
U90082 "SOT23-6" SOT23-6 2150.59,2889.76 r180 top
U90089 "CSP-12" CSP-12 499.02,1568.9 r0 top
U90104 "LCD39PIN-OK" LCD39PIN-OK 2775.59,3336.61 r90 top
U90115 "SOT_23_5" SOT_23_5 1450.79,542.32 r180 top
U90127 "SON10_2R50X1R00X0R50" SON10_2R50X1R00X0R50 4282.49,242.11 r0 top
U90128 "SOT_23_5" SOT_23_5 3287.4,648.62 r180 top
U90129 "QFN32P4X4" QFN32P4X4 4656.68,785.07 r0 top
U90131 "BAT_CR1220" BAT_CR1220 692.91,2360.24 r90 top
U90132 "CSP-12" CSP-12 783.46,1580.71 r0 top
U90133 "CSP-12" CSP-12 662.4,1580.71 r0 top
U90134 "DIP3_1X2P54" DIP3_1X2P54 5907.9,2736.2 r270 top
U90135 "CSP-12" CSP-12 937.01,1578.74 r0 top
U90136 "CSP-12" CSP-12 1361.96,2343.08 r180 top
USB2502 "USB30-L1" USB30-L1 1811.09,307.18 r0 top
Y1 "CRY4_3R20X2R50X0R80" CRY4_3R20X2R50X0R80 3448.83,893.71 r180 top
Y2 "3215_2PIN" 3215_2PIN 961.61,2813.98 r270 top

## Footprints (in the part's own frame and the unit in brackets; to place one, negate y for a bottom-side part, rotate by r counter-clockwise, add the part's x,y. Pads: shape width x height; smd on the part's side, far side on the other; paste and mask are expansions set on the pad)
3215_2PIN [mm]
  rect 0.65x1.3 smd: 1(0,0) 2(2.35,0)
  silkscreen extent -0.6,-0.8 2.9,0.8
BAT_CR1220 [mm]
  rect 3.099x4.064 smd: 1(0,8.348) 2(0,-8.134)
  round 1.2 hole 1.2 unplated: 3(0,-3.685)
  round 1.3 hole 1.3 unplated: 4(0,3.815)
  silkscreen extent -6.99,-6.61 7.47,8.76
C0201 [mm]
  rect 0.3x0.3 smd: 1(-0.25,0) 2(0.25,0)
  silkscreen extent -0.5,-0.25 0.5,0.25
C0402 [mm]
  rect 0.5x0.5 smd: 1(-0.4,0) 2(0.4,0)
  silkscreen extent -0.8,-0.4 0.8,0.4
C0603 [mm]
  rect 0.7x0.9 smd: 1(-0.7,0) 2(0.7,0)
  silkscreen extent -1.2,-0.6 1.2,0.6
C0805 [mm]
  rect 0.9x1.3 smd: 1(-0.85,0) 2(0.85,0)
  silkscreen extent -1.5,-0.8 1.5,0.8
C1206 [mil]
  rect 55x63 smd mask+2.5: 1(-49.21,0) 2(49.21,0)
  silkscreen extent -90,-46 90,46
CRY4_3R20X2R50X0R80 [mm]
  rect 1.4x1.2 smd: 1(-1.1,-0.85) 2(1.1,-0.85) 3(1.1,0.85) 4(-1.1,0.85)
  silkscreen extent -1.6,-2.02 1.6,1.26
CSP-12 [mm]
  round 0.24 smd mask+0.03: A1(0,0) A2(0.5,0) A3(1,0) B1(0,-0.5) B2(0.5,-0.5) B3(1,-0.5) C1(0,-1) C2(0.5,-1) C3(1,-1) D1(0,-1.5) D2(0.5,-1.5) D3(1,-1.5)
  silkscreen extent -0.3,-1.8 1.66,0.53
DC-044A [mm]
  oval 1.2x2.5 / inner oval 1.2x2.5 / far side oval 1.5x2.8 hole 0.787 slot 1.981 at 90 deg: 1(3.2,10.2) 2(-5.3,10.2) 3(0,10.2)
  oval 1x2.5 / inner oval 1x2.5 / far side oval 1.2x2.8 hole 0.6 slot 1.981 at 90 deg: 4(-6.2,3) 5(3.6,3)
  round 2.12 hole 2.12: 6(-0.009,3.991)
  silkscreen extent -6.3,0 4.5,11.6
DF40C-200DS-D4-OK [mm]
  rect 1.14x0.2 smd: 1(18.39,-7.32) 2(15.73,-7.32) 3(18.39,-6.92) 4(15.73,-6.92) 5(18.39,-6.52) 6(15.73,-6.52) 7(18.39,-6.12) 8(15.73,-6.12) 9(18.39,-5.72) 10(15.73,-5.72) 11(18.39,-5.32) 12(15.73,-5.32) 13(18.39,-4.92) 14(15.73,-4.92) 15(18.39,-4.52) 16(15.73,-4.52) 17(18.39,-4.12) 18(15.73,-4.12) 19(18.39,-3.72) 20(15.73,-3.72) 21(18.39,-3.32) 22(15.73,-3.32) 23(18.39,-2.92) 24(15.73,-2.92) 25(18.39,-2.52) 26(15.73,-2.52) 27(18.39,-2.12) 28(15.73,-2.12) 29(18.39,-1.72) 30(15.73,-1.72) 31(18.39,-1.32) 32(15.73,-1.32) 33(18.39,-0.92) 34(15.73,-0.92) 35(18.39,-0.52) 36(15.73,-0.52) 37(18.39,-0.12) 38(15.73,-0.12) 39(18.39,0.28) 40(15.73,0.28) 41(18.39,0.68) 42(15.73,0.68) 43(18.39,1.08) 44(15.73,1.08) 45(18.39,1.48) 46(15.73,1.48) 47(18.39,1.88) 48(15.73,1.88) 49(18.39,2.28) 50(15.73,2.28) 51(18.39,2.68) 52(15.73,2.68) 53(18.39,3.08) 54(15.73,3.08) 55(18.39,3.48) 56(15.73,3.48) 57(18.39,3.88) 58(15.73,3.88) 59(18.39,4.28) 60(15.73,4.28) 61(18.39,4.68) 62(15.73,4.68) 63(18.39,5.08) 64(15.73,5.08) 65(18.39,5.48) 66(15.73,5.48) 67(18.39,5.88) 68(15.73,5.88) 69(18.39,6.28) 70(15.73,6.28) 71(18.39,6.68) 72(15.73,6.68) 73(18.39,7.08) 74(15.73,7.08) 75(18.39,7.48) 76(15.73,7.48) 77(18.39,7.88) 78(15.73,7.88) 79(18.39,8.28) 80(15.73,8.28) 81(18.39,8.68) 82(15.73,8.68) 83(18.39,9.08) 84(15.73,9.08) 85(18.39,9.48) 86(15.73,9.48) 87(18.39,9.88) 88(15.73,9.88) 89(18.39,10.28) 90(15.73,10.28) 91(18.39,10.68) 92(15.73,10.68) 93(18.39,11.08) 94(15.73,11.08) 95(18.39,11.48) 96(15.73,11.48) 97(18.39,11.88) 98(15.73,11.88) 99(18.39,12.28) 100(15.73,12.28) 101(-15.68,-7.32) 102(-18.32,-7.32) 103(-15.68,-6.92) 104(-18.32,-6.92) 105(-15.68,-6.52) 106(-18.32,-6.52) 107(-15.68,-6.12) 108(-18.32,-6.12) 109(-15.68,-5.72) 110(-18.32,-5.72) 111(-15.68,-5.32) 112(-18.32,-5.32) 113(-15.68,-4.92) 114(-18.32,-4.92) 115(-15.68,-4.52) 116(-18.32,-4.52) 117(-15.68,-4.12) 118(-18.32,-4.12) 119(-15.68,-3.72) 120(-18.32,-3.72) 121(-15.68,-3.32) 122(-18.32,-3.32) 123(-15.68,-2.92) 124(-18.32,-2.92) 125(-15.68,-2.52) 126(-18.32,-2.52) 127(-15.68,-2.12) 128(-18.32,-2.12) 129(-15.68,-1.72) 130(-18.32,-1.72) 131(-15.68,-1.32) 132(-18.32,-1.32) 133(-15.68,-0.92) 134(-18.32,-0.92) 135(-15.68,-0.52) 136(-18.32,-0.52) 137(-15.68,-0.12) 138(-18.32,-0.12) 139(-15.68,0.28) 140(-18.32,0.28) 141(-15.68,0.68) 142(-18.32,0.68) 143(-15.68,1.08) 144(-18.32,1.08) 145(-15.68,1.48) 146(-18.32,1.48) 147(-15.68,1.88) 148(-18.32,1.88) 149(-15.68,2.28) 150(-18.32,2.28) 151(-15.68,2.68) 152(-18.32,2.68) 153(-15.68,3.08) 154(-18.32,3.08) 155(-15.68,3.48) 156(-18.32,3.48) 157(-15.68,3.88) 158(-18.32,3.88) 159(-15.68,4.28) 160(-18.32,4.28) 161(-15.68,4.68) 162(-18.32,4.68) 163(-15.68,5.08) 164(-18.32,5.08) 165(-15.68,5.48) 166(-18.32,5.48) 167(-15.68,5.88) 168(-18.32,5.88) 169(-15.68,6.28) 170(-18.32,6.28) 171(-15.68,6.68) 172(-18.32,6.68) 173(-15.68,7.08) 174(-18.32,7.08) 175(-15.68,7.48) 176(-18.32,7.48) 177(-15.68,7.88) 178(-18.32,7.88) 179(-15.68,8.28) 180(-18.32,8.28) 181(-15.68,8.68) 182(-18.32,8.68) 183(-15.68,9.08) 184(-18.32,9.08) 185(-15.68,9.48) 186(-18.32,9.48) 187(-15.68,9.88) 188(-18.32,9.88) 189(-15.68,10.28) 190(-18.32,10.28) 191(-15.68,10.68) 192(-18.32,10.68) 193(-15.68,11.08) 194(-18.32,11.08) 195(-15.68,11.48) 196(-18.32,11.48) 197(-15.68,11.88) 198(-18.32,11.88) 199(-15.68,12.28) 200(-18.32,12.28)
  round 6 / inner round 4 / far side round 6 hole 2.6: 201(16.51,-23.98) 202(-16.49,-23.98) 203(-16.51,23.97) 204(16.49,23.97)
  silkscreen extent -19.99,-27.48 20.03,27.5
DF40C_100DS [mm]
  rect 1.14x0.2 smd: 1(2.73,-1.5) 2(0.09,-1.5) 3(2.73,-1.9) 4(0.09,-1.9) 5(2.73,-2.3) 6(0.09,-2.3) 7(2.73,-2.7) 8(0.09,-2.7) 9(2.73,-3.1) 10(0.09,-3.1) 11(2.73,-3.5) 12(0.09,-3.5) 13(2.73,-3.9) 14(0.09,-3.9) 15(2.73,-4.3) 16(0.09,-4.3) 17(2.73,-4.7) 18(0.09,-4.7) 19(2.73,-5.1) 20(0.09,-5.1) 21(2.73,-5.5) 22(0.09,-5.5) 23(2.73,-5.9) 24(0.09,-5.9) 25(2.73,-6.3) 26(0.09,-6.3) 27(2.73,-6.7) 28(0.09,-6.7) 29(2.73,-7.1) 30(0.09,-7.1) 31(2.73,-7.5) 32(0.09,-7.5) 33(2.73,-7.9) 34(0.09,-7.9) 35(2.73,-8.3) 36(0.09,-8.3) 37(2.73,-8.7) 38(0.09,-8.7) 39(2.73,-9.1) 40(0.09,-9.1) 41(2.73,-9.5) 42(0.09,-9.5) 43(2.73,-9.9) 44(0.09,-9.9) 45(2.73,-10.3) 46(0.09,-10.3) 47(2.73,-10.7) 48(0.09,-10.7) 49(2.73,-11.1) 50(0.09,-11.1) 51(2.73,-11.5) 52(0.09,-11.5) 53(2.73,-11.9) 54(0.09,-11.9) 55(2.73,-12.3) 56(0.09,-12.3) 57(2.73,-12.7) 58(0.09,-12.7) 59(2.73,-13.1) 60(0.09,-13.1) 61(2.73,-13.5) 62(0.09,-13.5) 63(2.73,-13.9) 64(0.09,-13.9) 65(2.73,-14.3) 66(0.09,-14.3) 67(2.73,-14.7) 68(0.09,-14.7) 69(2.73,-15.1) 70(0.09,-15.1) 71(2.73,-15.5) 72(0.09,-15.5) 73(2.73,-15.9) 74(0.09,-15.9) 75(2.73,-16.3) 76(0.09,-16.3) 77(2.73,-16.7) 78(0.09,-16.7) 79(2.73,-17.1) 80(0.09,-17.1) 81(2.73,-17.5) 82(0.09,-17.5) 83(2.73,-17.9) 84(0.09,-17.9) 85(2.73,-18.3) 86(0.09,-18.3) 87(2.73,-18.7) 88(0.09,-18.7) 89(2.73,-19.1) 90(0.09,-19.1) 91(2.73,-19.5) 92(0.09,-19.5) 93(2.73,-19.9) 94(0.09,-19.9) 95(2.73,-20.3) 96(0.09,-20.3) 97(2.73,-20.7) 98(0.09,-20.7) 99(2.73,-21.1) 100(0.09,-21.1)
  silkscreen extent 0,-22.54 2.84,0.01
DIP2PIN-2P54MM [mm]
  rect 1.3x1.3 / inner rect 1.5x1.5 / far side rect 1.5x1.5 hole 0.9 mask+0.1: 1(0,0)
  round 1.3 / inner round 1.5 / far side round 1.5 hole 0.9 mask+0.1: 2(0,-2.54)
  silkscreen extent -1.25,-3.79 1.25,1.25
DIP3_1X2P54 [mm]
  round 1.3 / inner round 1.3 / far side round 1.6 hole 1: 1(-2.54,0) 2(0,0) 3(2.54,0)
  silkscreen extent -3.81,-1.9 3.81,1.27
DIP4PIN-2_54MM-2X2 [mm]
  round 1.6 / inner round 1.27 / far side round 1.6 hole 0.889: 1(2.54,-2.54) 2(2.54,0) 3(0,-2.54)
  rect 1.6x1.6 hole 0.889: 4(0,0)
DIP40PIN_2D54MM [mm]
  round 1.5 / inner round 1.15 / far side round 1.5 hole 0.9: 1(0,-2.54) 2(0,0) 3(2.54,-2.54) 4(2.54,0) 5(5.08,-2.54) 6(5.08,0) 7(7.62,-2.54) 8(7.62,0) 9(10.16,-2.54) 10(10.16,0) 11(12.7,-2.54) 12(12.7,0) 13(15.24,-2.54) 14(15.24,0) 15(17.78,-2.54) 16(17.78,0) 17(20.32,-2.54) 18(20.32,0) 19(22.86,-2.54) 20(22.86,0) 21(25.4,-2.54) 22(25.4,0) 23(27.94,-2.54) 24(27.94,0) 25(30.48,-2.54) 26(30.48,0) 27(33.02,-2.54) 28(33.02,0) 29(35.56,-2.54) 30(35.56,0) 31(38.1,-2.54) 32(38.1,0) 33(40.64,-2.54) 34(40.64,0) 35(43.18,-2.54) 36(43.18,0) 37(45.72,-2.54) 38(45.72,0) 39(48.26,-2.54) 40(48.26,0)
DO_214AC [mm]
  rect 2.5x2 smd mask+0.05: 1(-2,0) 2(2,0)
  silkscreen extent -3.54,-1.65 3.68,1.65
E0402N [mil]
  rrect0% 25x25 smd: 1(-25,0) 2(25,0)
  Top region: 12.5,7 6,0.5 12.75,-6.25 12.75,6.5 12.5,6.5 12.5,7
  Top region: 14.5,11 3.75,0.25 14.75,-10.75 14.75,10.5 14.5,10.5 14.5,11
  Top region: -12,-6.5 -5.5,0 -12.25,6.75 -12.25,-6 -12,-6 -12,-6.5
  Top region: -14,-10.5 -3.25,0.25 -14.25,11.25 -14.25,-10 -14,-10 -14,-10.5
  Top lines w2: 20,7.5 12.5,7.5 ; 20,-7 12.5,-7 ; 18.5,6 11,6 ; 18.5,-5.5 11,-5.5 ; 17.5,-4 10,-4 ; 17,4.5 9.5,4.5 ; 16.5,-3 9,-3 ; 16,3 8.5,3 ; 15.5,-2 8,-2 ; 14.5,2 7,2 ; 14,-1 6.5,-1 ; 13.5,1 6,1 ; 13,0 5.5,0 ; -5,0.5 -12.5,0.5 ; -5.5,-0.5 -13,-0.5 ; -6,1.5 -13.5,1.5 ; -6.5,-1.5 -14,-1.5 ; -7.5,2.5 -15,2.5 ; -8,-2.5 -15.5,-2.5 ; -8.5,3.5 -16,3.5 ; -9,-4 -16.5,-4 ; -9.5,4.5 -17,4.5 ; -10.5,6 -18,6 ; -10.5,-5.5 -18,-5.5 ; -12,7.5 -19.5,7.5 ; -12,-7 -19.5,-7
  silkscreen extent -45,-22 45,22
ESD0402 [mil]
  rect 33.3x33.3 smd: 1(-25,0) 2(25,0)
  silkscreen extent -55,-20 75,20
ESD0402_1XD5 [mm]
  rect 0.4x0.55 smd: 1(-0.45,0) 2(0.45,0)
  Top region: 0.318,0.178 0.152,0.013 0.324,-0.159 0.324,0.165 0.318,0.165 0.318,0.178
  Top region: 0.368,0.279 0.095,0.006 0.375,-0.273 0.375,0.267 0.368,0.267 0.368,0.279
  Top region: -0.305,-0.165 -0.14,0 -0.311,0.171 -0.311,-0.152 -0.305,-0.152 -0.305,-0.165
  Top region: -0.356,-0.267 -0.083,0.006 -0.362,0.286 -0.362,-0.254 -0.356,-0.254 -0.356,-0.267
  Top lines w0.051: 0.508,0.191 0.317,0.191 ; 0.508,-0.178 0.318,-0.178 ; 0.47,0.152 0.279,0.152 ; 0.47,-0.14 0.279,-0.14 ; 0.445,-0.102 0.254,-0.102 ; 0.432,0.114 0.241,0.114 ; 0.419,-0.076 0.229,-0.076 ; 0.406,0.076 0.216,0.076 ; 0.394,-0.051 0.203,-0.051 ; 0.368,0.051 0.178,0.051 ; 0.356,-0.025 0.165,-0.025 ; 0.343,0.025 0.152,0.025 ; 0.33,0 0.14,0 ; -0.127,0.013 -0.318,0.013 ; -0.14,-0.013 -0.33,-0.013 ; -0.152,0.038 -0.343,0.038 ; -0.165,-0.038 -0.356,-0.038 ; -0.191,0.063 -0.381,0.063 ; -0.203,-0.064 -0.394,-0.064 ; -0.216,0.089 -0.406,0.089 ; -0.229,-0.102 -0.419,-0.102 ; -0.241,0.114 -0.432,0.114 ; -0.267,0.152 -0.457,0.152 ; -0.267,-0.14 -0.457,-0.14 ; -0.305,0.19 -0.495,0.19 ; -0.305,-0.178 -0.495,-0.178
  silkscreen extent -0.85,-0.4 0.85,0.4
FH35C_31P_0_6SHW [mil]
  rect 10x54 smd mask+2: 1(0,0) 2(11.81,113.18) 3(23.62,0) 4(35.43,113.18) 5(47.24,0) 6(59.05,113.18) 7(70.87,0) 8(82.68,113.18) 9(94.49,0) 10(106.3,113.18) 11(118.11,0) 12(129.92,113.18) 13(141.73,0) 14(153.54,113.18) 15(165.35,0) 16(177.17,113.18) 17(188.98,0) 18(200.79,113.18) 19(212.6,0) 20(224.41,113.18) 21(236.22,0) 22(248.03,113.18) 23(259.84,0) 24(271.65,113.18) 25(283.46,0) 26(295.28,113.18) 27(307.09,0) 28(318.9,113.18) 29(330.71,0) 30(342.52,113.18) 31(354.33,0)
  rect 15.75x59.06 smd mask+2.95: 32(381.89,13.18) 33(-27.56,13.18)
  silkscreen extent -42,-67 394,131
FPC15PIN-1.0MM-LS [mm]
  rect 0.6x1.775 smd: 1(0,0) 2(1,0) 3(2,0) 4(3,0) 5(4,0) 6(5,0) 7(6,0) 8(7,0) 9(8,0) 10(9,0) 11(10,0) 12(11,0) 13(12,0) 14(13,0) 15(14,0) 16(0,-3.125) 17(1,-3.125) 18(2,-3.125) 19(3,-3.125) 20(4,-3.125) 21(5,-3.125) 22(6,-3.125) 23(7,-3.125) 24(8,-3.125) 25(9,-3.125) 26(10,-3.125) 27(11,-3.125) 28(12,-3.125) 29(13,-3.125) 30(14,-3.125)
  silkscreen extent -3.57,-5.06 17.5,2.4
HDMIA19S [mm]
  rect 0.3x2.6 smd: 1(-4.5,0) 2(-4,0) 3(-3.5,0) 4(-3,0) 5(-2.5,0) 6(-2,0) 7(-1.5,0) 8(-1,0) 9(-0.5,0) 10(0,0) 11(0.5,0) 12(1,0) 13(1.5,0) 14(2,0) 15(2.5,0) 16(3,0) 17(3.5,0) 18(4,0) 19(4.5,0)
  oval 1.3x3.2 hole 0.787 slot 2.692 at 90 deg: 20(7.25,1) 21(-7.25,1)
  oval 1.3x2.2 hole 0.787 slot 1.676 at 90 deg: 22(-7.25,6.96) 23(7.25,6.96)
  silkscreen extent -7.5,0 7.5,9.45
HOLE_D5_3D [mm]
  round 3.8 hole 2.8: 1(0,0)
IND-5020 [mm]
  rect 1.4x2.8 smd: 1(-2.2,0) 2(2.2,0)
  silkscreen extent -2.7,-2.55 2.7,2.55
IND_3X3 [mm]
  rect 3x1.1 smd: 1(0,-0.95) 2(0,0.95)
  silkscreen extent -1.73,-1.71 1.72,1.72
IND_303015 [mil]
  rect 39x118 smd mask+3: 1(-44.85,0) 2(43.43,0)
  silkscreen extent -70,-65 70,65
L0402 [mm]
  rect 0.5x0.5 smd: 1(-0.45,0) 2(0.45,0)
  silkscreen extent -0.8,-0.35 0.8,0.35
LCD39PIN-OK [mil]
  rect 54x10 smd: 1(0,0) 2(-113.18,11.81) 3(0,23.62) 4(-113.18,35.43) 5(0,47.24) 6(-113.18,59.06) 7(0,70.87) 8(-113.18,82.68) 9(0,94.49) 10(-113.18,106.3) 11(0,118.11) 12(-113.18,129.92) 13(0,141.73) 14(-113.18,153.54) 15(0,165.35) 16(-113.18,177.17) 17(0,188.98) 18(-113.18,200.79) 19(0,212.6) 20(-113.18,224.41) 21(0,236.22) 22(-113.18,248.03) 23(0,259.84) 24(-113.18,271.65) 25(0,283.46) 26(-113.18,295.28) 27(0,307.09) 28(-113.18,318.9) 29(0,330.71) 30(-113.18,342.52) 31(0,354.33) 32(-113.18,366.14) 33(0,377.95) 34(-113.18,389.76) 35(0,401.57) 36(-113.18,413.39) 37(0,425.2) 38(-113.18,437.01) 39(0,448.82)
  rect 59.06x15.75 smd: 40(-13.18,476.38) 41(-13.18,-27.56)
  silkscreen extent -130,-33 63,483
LED0603 [mm]
  rect 0.8x0.8 smd: 1(-0.869,0.001) 2(0.869,-0.001)
  silkscreen extent -1.41,-0.65 1.41,0.65
M2_NGFF_KEY_E_1 [mm]
  rect 0.3x1.6 smd: 1(-9.25,3.725) 2(-9,-3.725) 3(-8.75,3.725) 4(-8.5,-3.725) 5(-8.25,3.725) 6(-8,-3.725) 7(-7.75,3.725) 8(-7.5,-3.725) 9(-7.25,3.725) 10(-7,-3.725) 11(-6.75,3.725) 12(-6.5,-3.725) 13(-6.25,3.725) 14(-6,-3.725) 15(-5.75,3.725) 16(-5.5,-3.725) 17(-5.25,3.725) 18(-5,-3.725) 19(-4.75,3.725) 20(-4.5,-3.725) 21(-4.25,3.725) 22(-4,-3.725) 23(-3.75,3.725) 32(-1.5,-3.725) 33(-1.25,3.725) 34(-1,-3.725) 35(-0.75,3.725) 36(-0.5,-3.725) 37(-0.25,3.725) 38(0,-3.725) 39(0.25,3.725) 40(0.5,-3.725) 41(0.75,3.725) 42(1,-3.725) 43(1.25,3.725) 44(1.5,-3.725) 45(1.75,3.725) 46(2,-3.725) 47(2.25,3.725) 48(2.5,-3.725) 49(2.75,3.725) 50(3,-3.725) 51(3.25,3.725) 52(3.5,-3.725) 53(3.75,3.725) 54(4,-3.725) 55(4.25,3.725) 56(4.5,-3.725) 57(4.75,3.725) 58(5,-3.725) 59(5.25,3.725) 60(5.5,-3.725) 61(5.75,3.725) 62(6,-3.725) 63(6.25,3.725) 64(6.5,-3.725) 65(6.75,3.725) 66(7,-3.725) 67(7.25,3.75) 68(7.5,-3.725) 69(7.75,3.725) 70(8,-3.725) 71(8.25,3.725) 72(8.5,-3.725) 73(8.75,3.725) 74(9,-3.725) 75(9.25,3.725)
  rect 1.2x2.8 smd: 76(10.35,3.025) 77(-10.35,3.025)
  round 1.2 hole 1.2 unplated: 78(-10,-1.475)
  round 1.7 hole 1.7 unplated: 79(10,-1.475)
  silkscreen extent -10.97,-31.58 10.97,4.84
MCZ1210AH900L2 [mm]
  rect 0.3x0.5 smd: 1(0,0) 2(0.55,0) 3(0.55,1.2) 4(0,1.2)
  silkscreen extent -0.25,0 0.8,1.25
MLP14_2R50X2R50X0R80 [mm]
  rect 0.6x0.3 smd: 1(-1.21,0.5) 2(-1.21,0) 3(-1.21,-0.5) 8(1.21,-0.5) 9(1.21,0) 10(1.21,0.5)
  rect 0.3x0.6 smd: 4(-0.75,-1.21) 5(-0.25,-1.21) 6(0.25,-1.21) 7(0.75,-1.21) 11(0.75,1.21) 12(0.25,1.21) 13(-0.25,1.21) 14(-0.75,1.21)
  rect 1.45x1.45 smd: 15(0,0)
  silkscreen extent -2.48,-1.25 1.25,1.25
MSOP8 [mm]
  rect 1x0.4 smd: 1(-2.4,0.947) 2(-2.4,0.297) 3(-2.4,-0.353) 4(-2.4,-1.003) 5(2.4,-1.003) 6(2.4,-0.353) 7(2.4,0.297) 8(2.4,0.947)
  silkscreen extent -3.91,-1.52 3.05,1.52
PJ-327A [mm]
  round 1.5 hole 1.5: 1(0,0) 8(7,0)
  oval 2x1.2 / inner oval 1.6x0.8 / far side oval 2x1.2 hole 0.686 slot 1.499 at 0 deg: 2(-0.2,2.05) 5(-0.2,-2.65)
  rect 1.3x2 smd: 3(6.8,3.55) 4(9.1,3.55) 6(3.1,-3.55) 7(8.6,-3.55)
  silkscreen extent -4.59,-3.2 9.61,3.2
QFN12_2R00X3R00X1R00 [mm]
  rect 1.5x0.25 smd: 1(-0.55,0.5) 2(-0.55,-0.5) 7(0.55,0)
  rect 0.25x0.7 smd: 3(-0.75,-1.45) 4(-0.25,-1.45) 5(0.25,-1.45) 6(0.75,-1.45) 9(0.75,1.45) 10(0.25,1.45) 11(-0.25,1.45) 12(-0.75,1.45)
  rect 0.7x0.25 smd: 8(0.95,0.5)
  silkscreen extent -1.81,-1.5 1,1.5
QFN24 [mm]
  oval 0.25x1 smd: 1(-1.25,-2.2) 2(-0.75,-2.2) 3(-0.25,-2.2) 4(0.25,-2.2) 5(0.75,-2.2) 6(1.25,-2.2) 13(1.25,2.2) 14(0.75,2.2) 15(0.25,2.2) 16(-0.25,2.2) 17(-0.75,2.2) 18(-1.25,2.2)
  oval 1x0.25 smd: 7(2.2,-1.25) 8(2.2,-0.75) 9(2.2,-0.25) 10(2.2,0.25) 11(2.2,0.75) 12(2.2,1.25) 19(-2.2,1.25) 20(-2.2,0.75) 21(-2.2,0.25) 22(-2.2,-0.25) 23(-2.2,-0.75) 24(-2.2,-1.25)
  rrect100% 0.6x0.6 smd: 25(-0.037,-0.041)
  Top region: -1.253,0.95 -1.242,1.028 -1.212,1.101 -1.164,1.164 -1.101,1.212 -1.028,1.242 -0.95,1.253 -0.95,1.25 0.95,1.253 1.028,1.242 1.101,1.212 1.164,1.164 1.212,1.101 1.242,1.028 1.253,0.95 1.25,0.95 1.253,-0.95 1.242,-1.028 1.212,-1.101 1.164,-1.164 1.101,-1.212 1.028,-1.242 0.95,-1.253 0.95,-1.25 -0.95,-1.253 -1.028,-1.242 -1.101,-1.212 -1.164,-1.164 -1.212,-1.101 -1.242,-1.028 -1.253,-0.95 -1.25,-0.95 -1.25,0.95
  silkscreen extent -2.03,-2.98 2.01,2
QFN32P4X4 [mm]
  rect 0.75x0.23 smd: 1(-2.025,1.4) 2(-2.025,1) 3(-2.025,0.6) 4(-2.025,0.2) 5(-2.025,-0.2) 6(-2.025,-0.6) 7(-2.025,-1) 8(-2.025,-1.4) 17(2.025,-1.4) 18(2.025,-1) 19(2.025,-0.6) 20(2.025,-0.2) 21(2.025,0.2) 22(2.025,0.6) 23(2.025,1) 24(2.025,1.4)
  rect 0.23x0.75 smd: 9(-1.4,-1.95) 10(-1,-1.95) 11(-0.6,-1.95) 12(-0.2,-1.95) 13(0.2,-1.95) 14(0.6,-1.95) 15(1,-1.95) 16(1.4,-1.95) 25(1.4,1.95) 26(1,1.95) 27(0.6,1.95) 28(0.2,1.95) 29(-0.2,1.95) 30(-0.6,1.95) 31(-1,1.95) 32(-1.4,1.95)
  rect 2.2x2.2 smd: 33(0,0)
  silkscreen extent -3.1,-2 2,2
R0201 [mm]
  rect 0.3x0.3 smd: 1(-0.25,0) 2(0.25,0)
  silkscreen extent -0.5,-0.25 0.5,0.25
R0402 [mm]
  rect 0.5x0.5 smd: 1(-0.4,0) 2(0.4,0)
  silkscreen extent -0.8,-0.4 0.8,0.4
R0603 [mm]
  rect 0.7x0.9 smd: 1(-0.7,0) 2(0.7,0)
  silkscreen extent -1.2,-0.6 1.2,0.6
R1206 [mm]
  rect 1.4x1.6 smd mask+0.05: 1(-1.3,0) 2(1.3,0)
  silkscreen extent -2.2,-1 2.2,1
RJ45_HRK1 [mm]
  rect 1.524x1.524 hole 0.9 mask+0.05: 1(0,0)
  round 1.524 / inner round 1.1 / far side round 1.524 hole 0.9 mask+0.05: 2(1.27,-2.54) 3(2.54,0) 4(3.81,-2.54) 5(5.08,0) 6(6.35,-2.54) 7(7.62,0) 8(8.89,-2.54) 9(10.16,0) 10(11.43,-2.54) 11(0,-5.06) 12(2.54,-6.33) 13(8.89,-6.33) 14(11.43,-5.06) 18(12.36,-12.95)
  round 1.524 hole 1.02 mask+0.05: 15(-0.92,-12.95) 16(1.62,-12.95) 17(9.82,-12.95)
  round 2 / inner round 2.2 / far side round 2.2 hole 1.6 mask+0.15: 19(-2.13,-5.84) 20(13.57,-5.84)
  round 3.25 hole 3.25: 21(0.005,-8.89) 22(11.435,-8.89)
  silkscreen extent -2.33,-19.64 13.77,1.71
SMD_1D25X2PIN_90 [mm]
  rect 0.8x1.6 smd: 1(-1.25,0) 2(0,0)
  rect 2.1x3 smd: 3(-3.85,2.82) 4(2.6,2.82)
  silkscreen extent -5,-0.9 3.72,4.47
SMD_TCM0605T [mm]
  rect 0.3x0.23 smd: 1(0,0) 2(0,-0.48) 3(0.55,-0.48) 4(0.55,0)
  silkscreen extent -0.25,-0.65 0.75,0.2
SOD_123 [mm]
  rect 1x1 smd: 1(-1.8,0) 2(1.8,0)
  silkscreen extent -1.11,-0.9 1.13,0.9
SOD_323 [mm]
  rect 0.8x0.6 smd mask+0.05: 1(-1.2,0) 2(1.2,0)
  silkscreen extent -0.67,-0.65 0.64,0.65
